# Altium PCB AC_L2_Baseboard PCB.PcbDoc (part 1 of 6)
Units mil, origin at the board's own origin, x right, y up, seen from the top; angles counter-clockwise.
Board outline 7290 x 7055 mil, 4 copper layers (Top Layer, Layer 1, Layer 2, Bottom Layer), stack 70.356 mil thick; 510 components, 285 nets, 1364 pads, 522 vias.
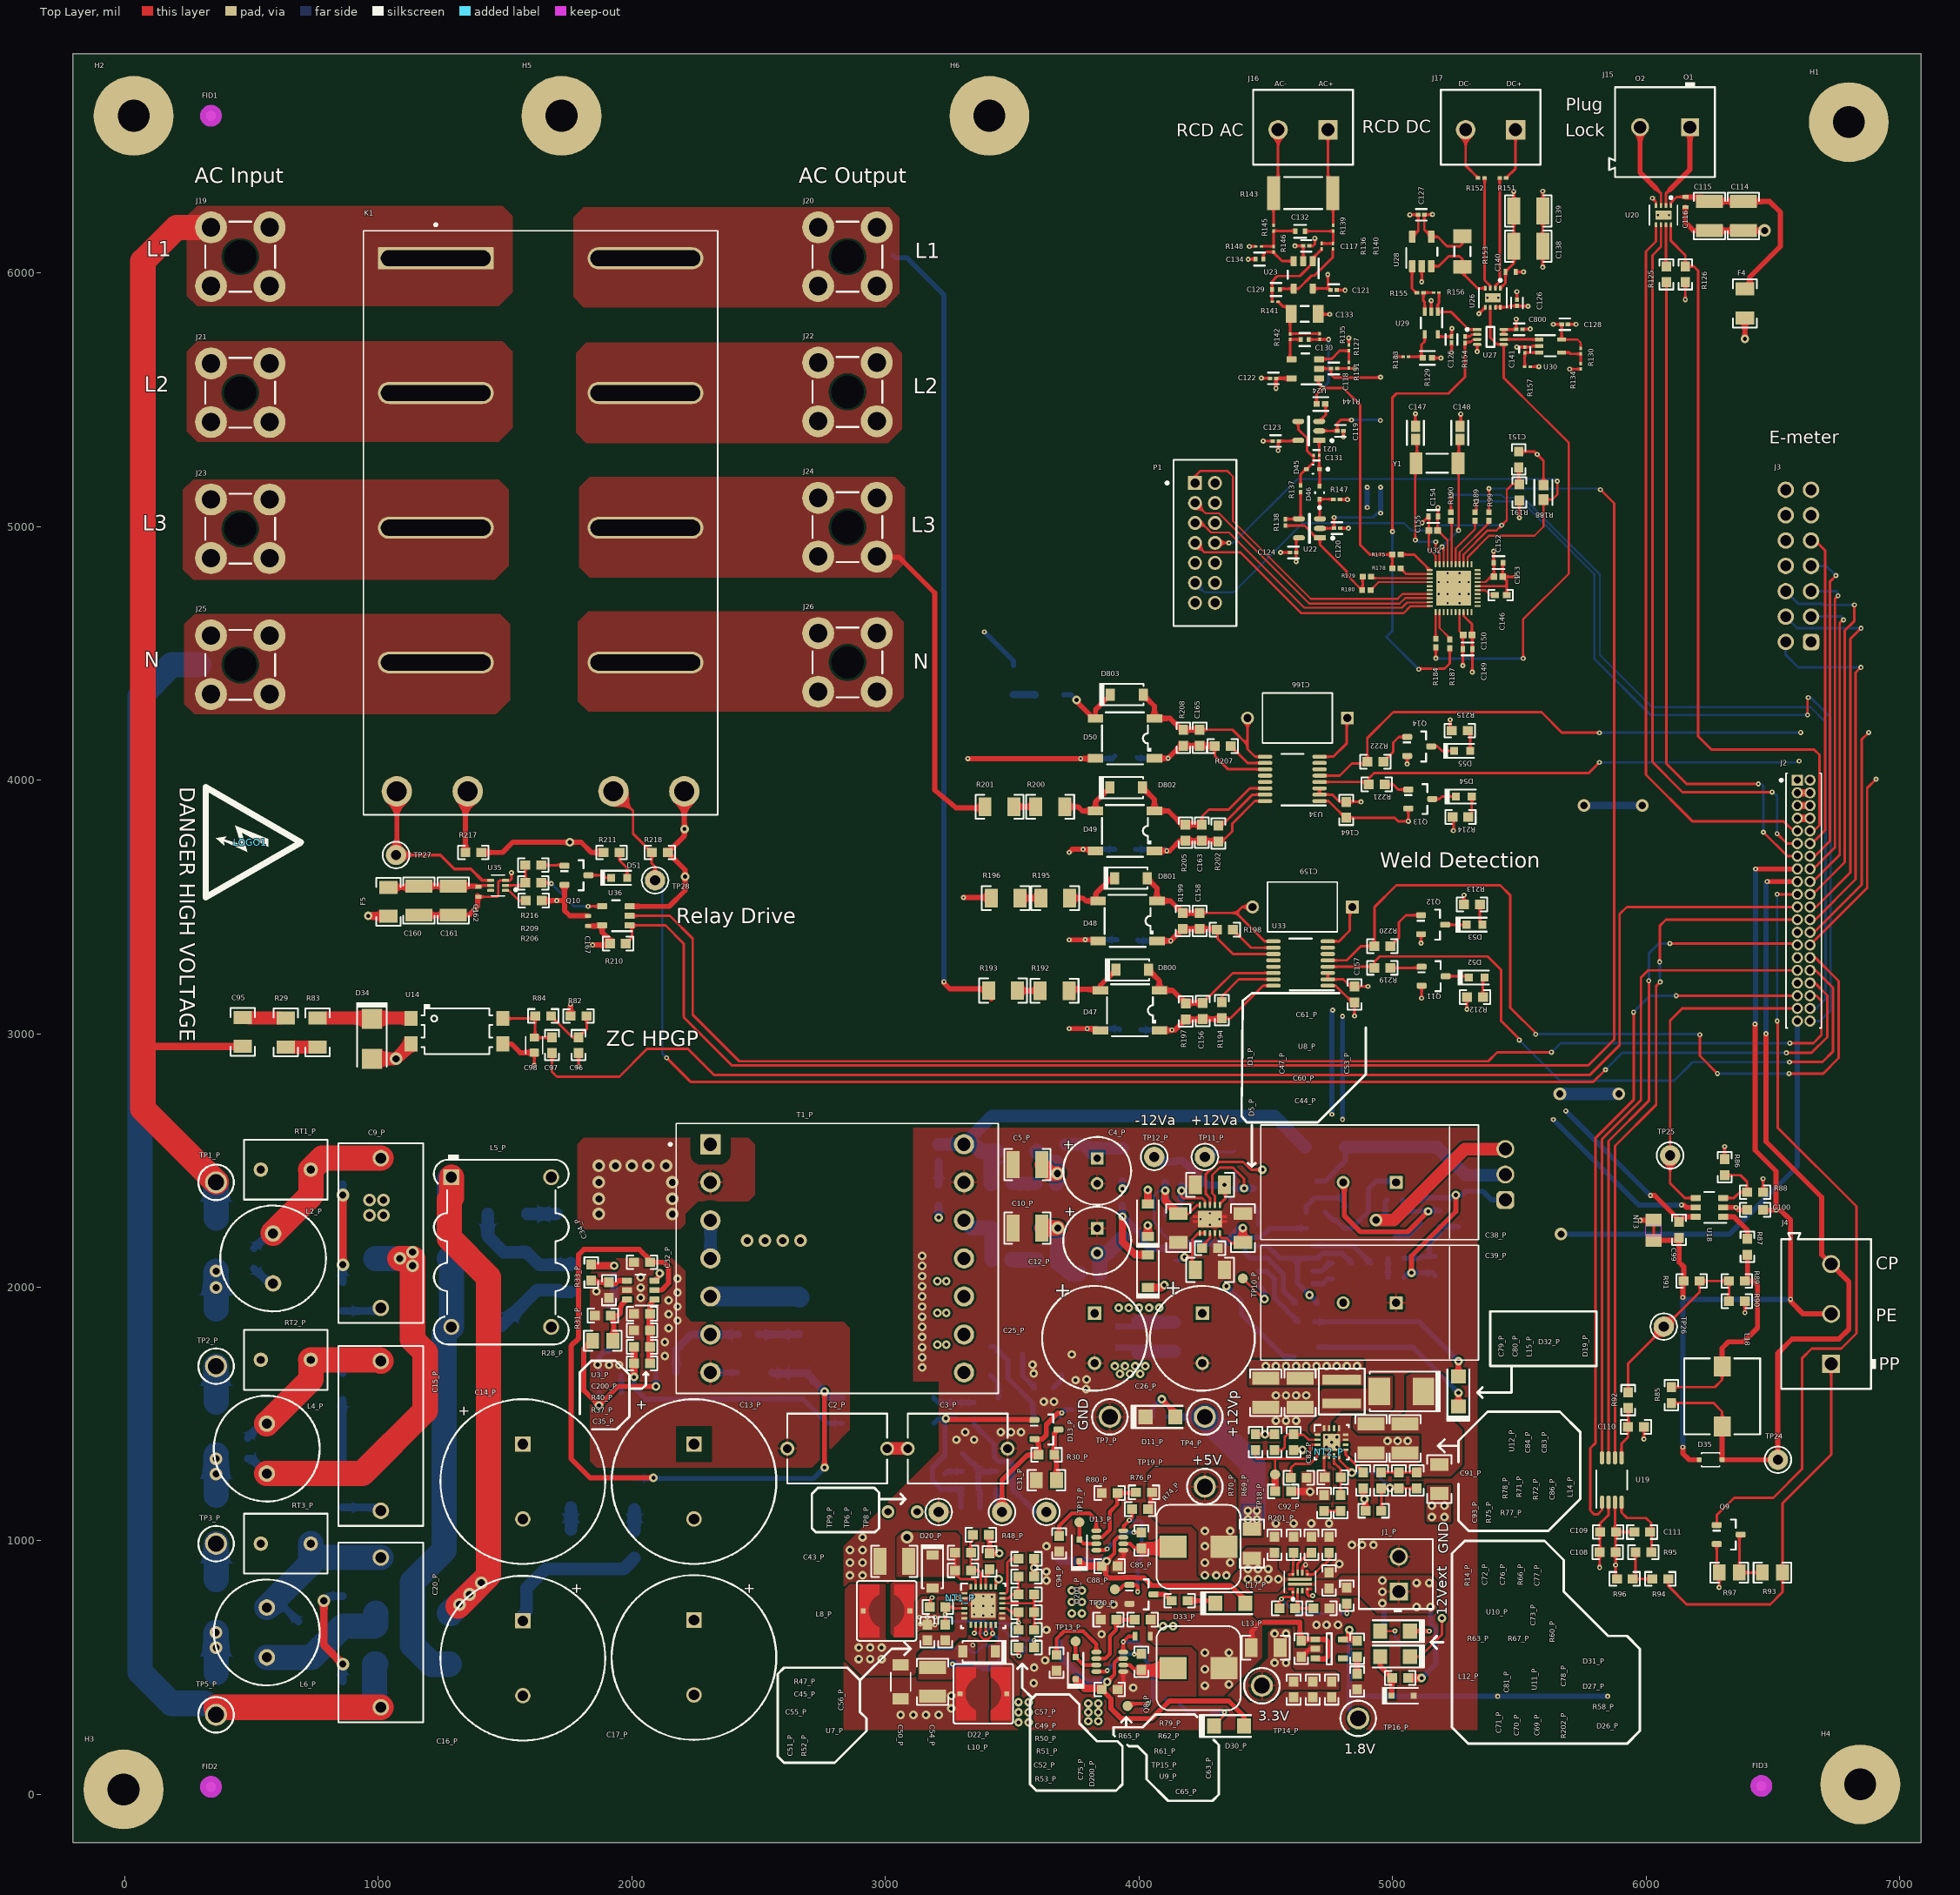
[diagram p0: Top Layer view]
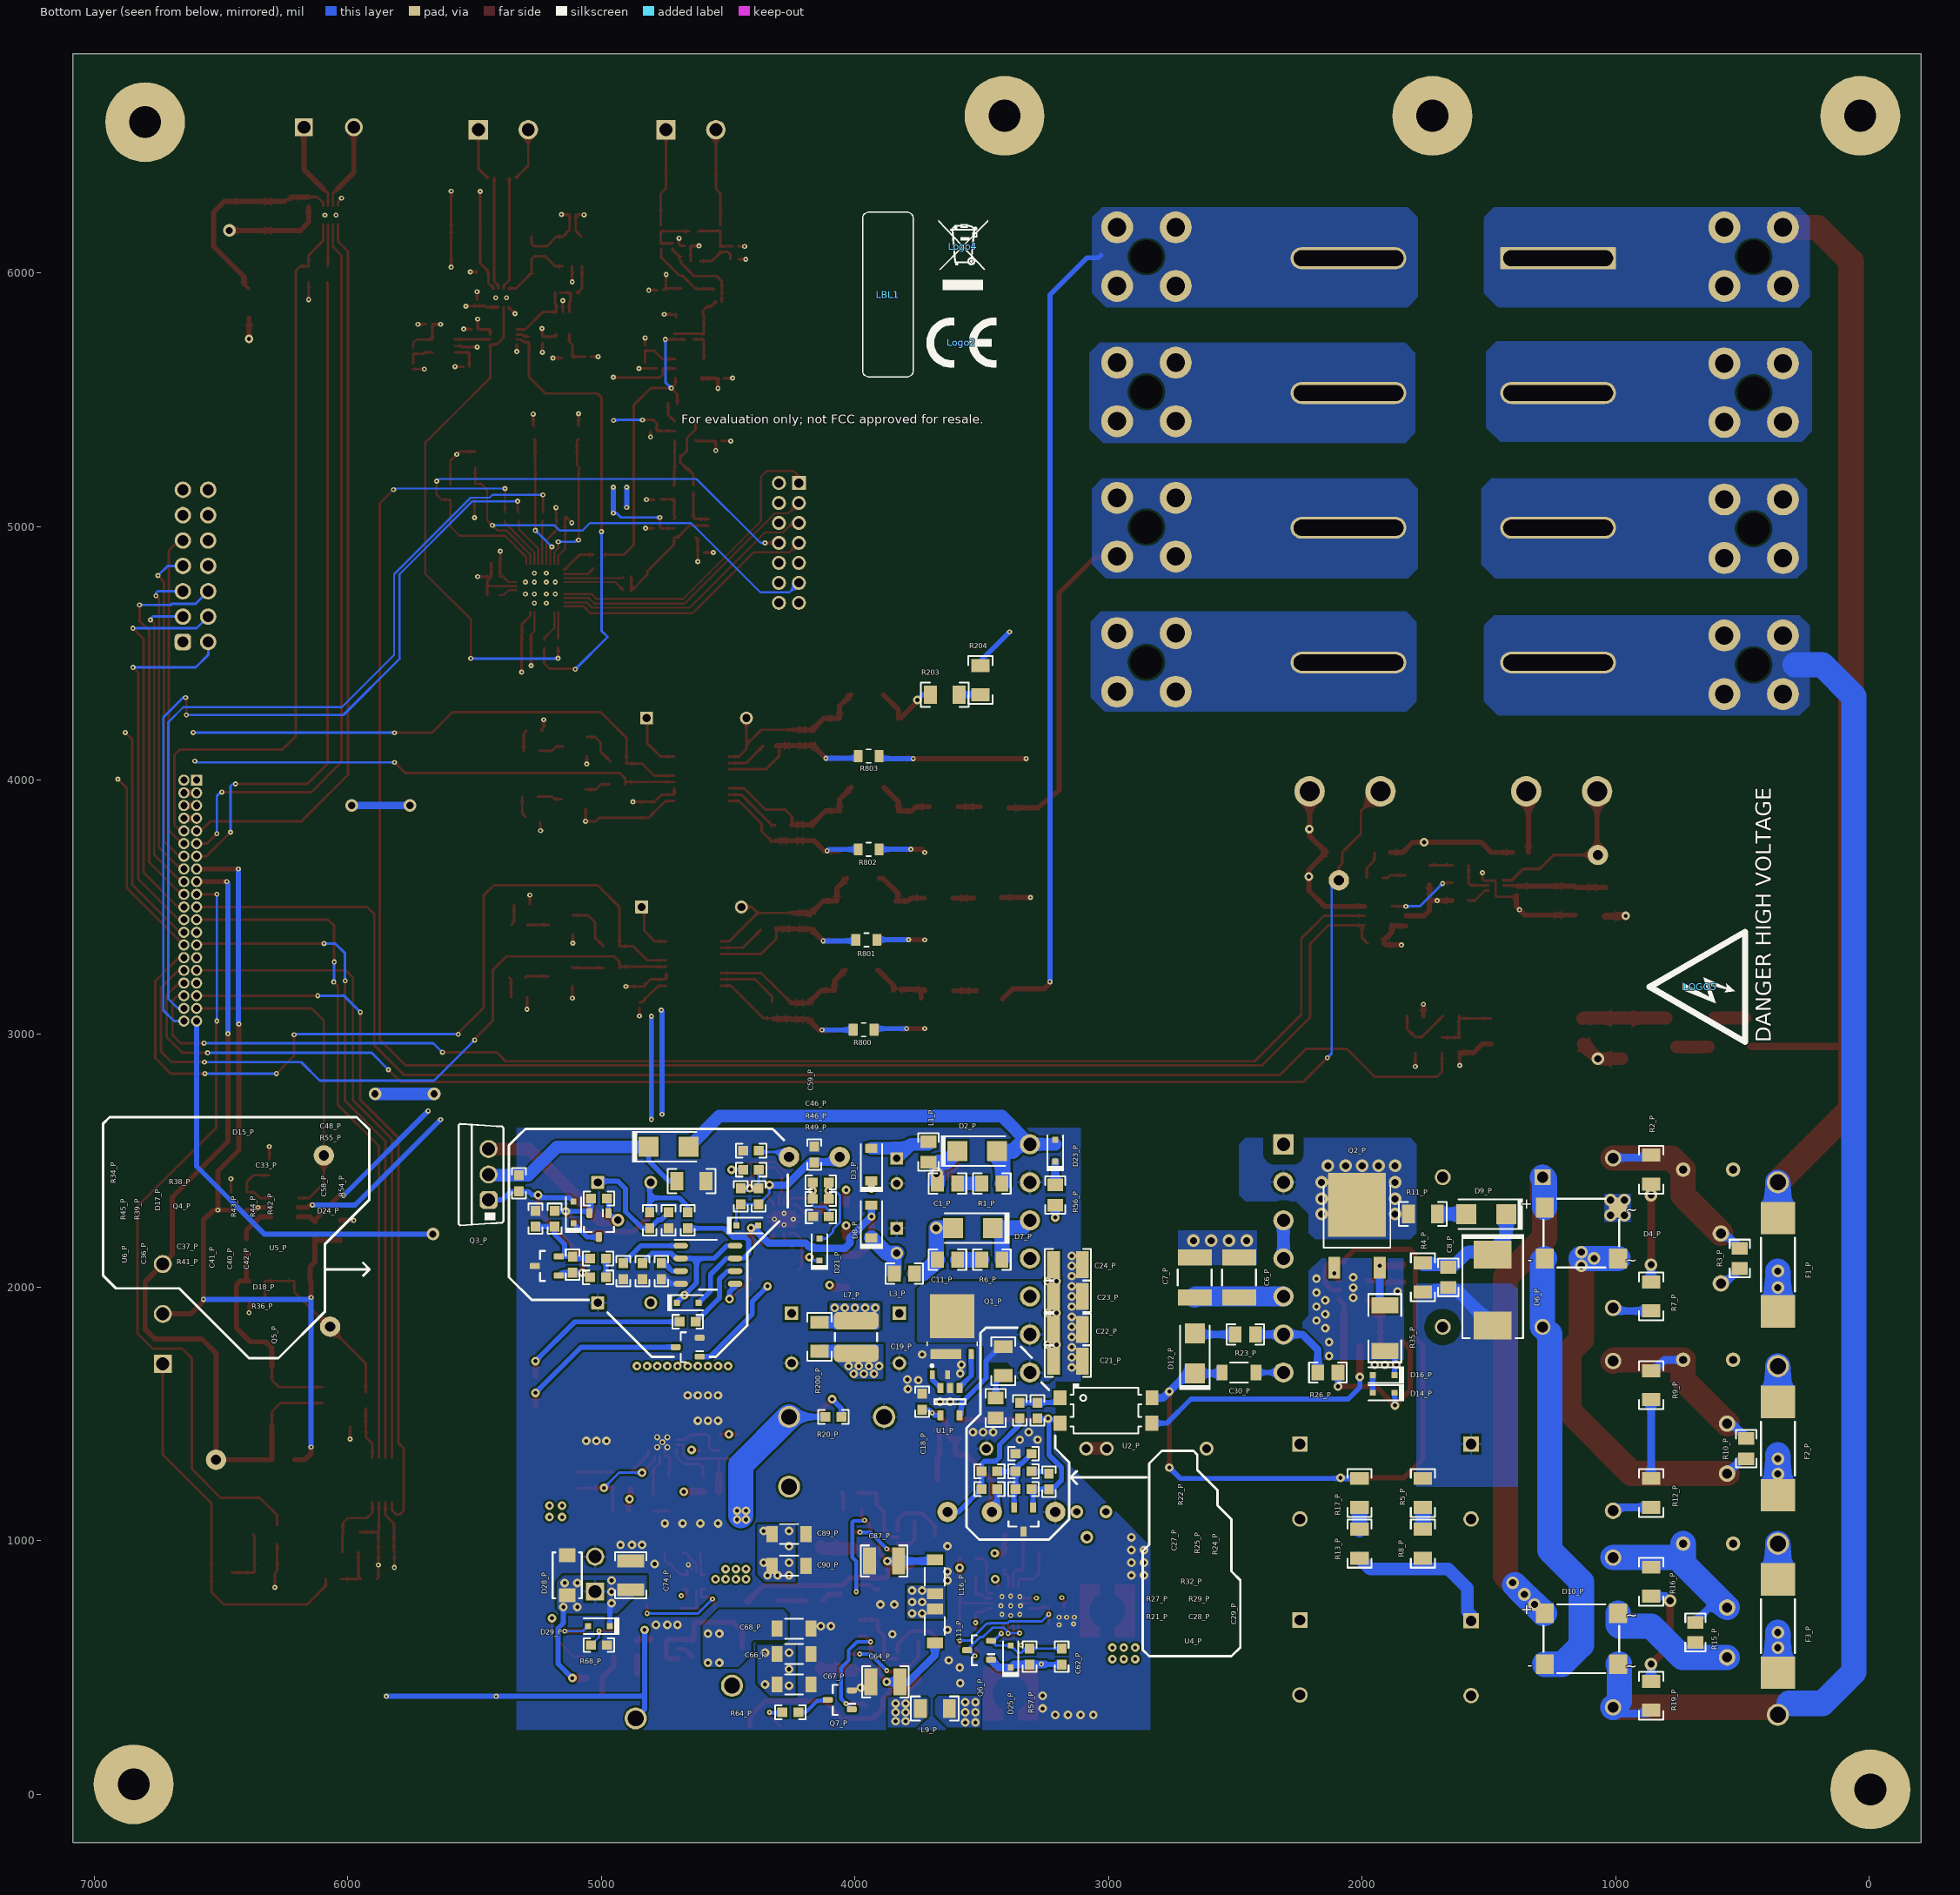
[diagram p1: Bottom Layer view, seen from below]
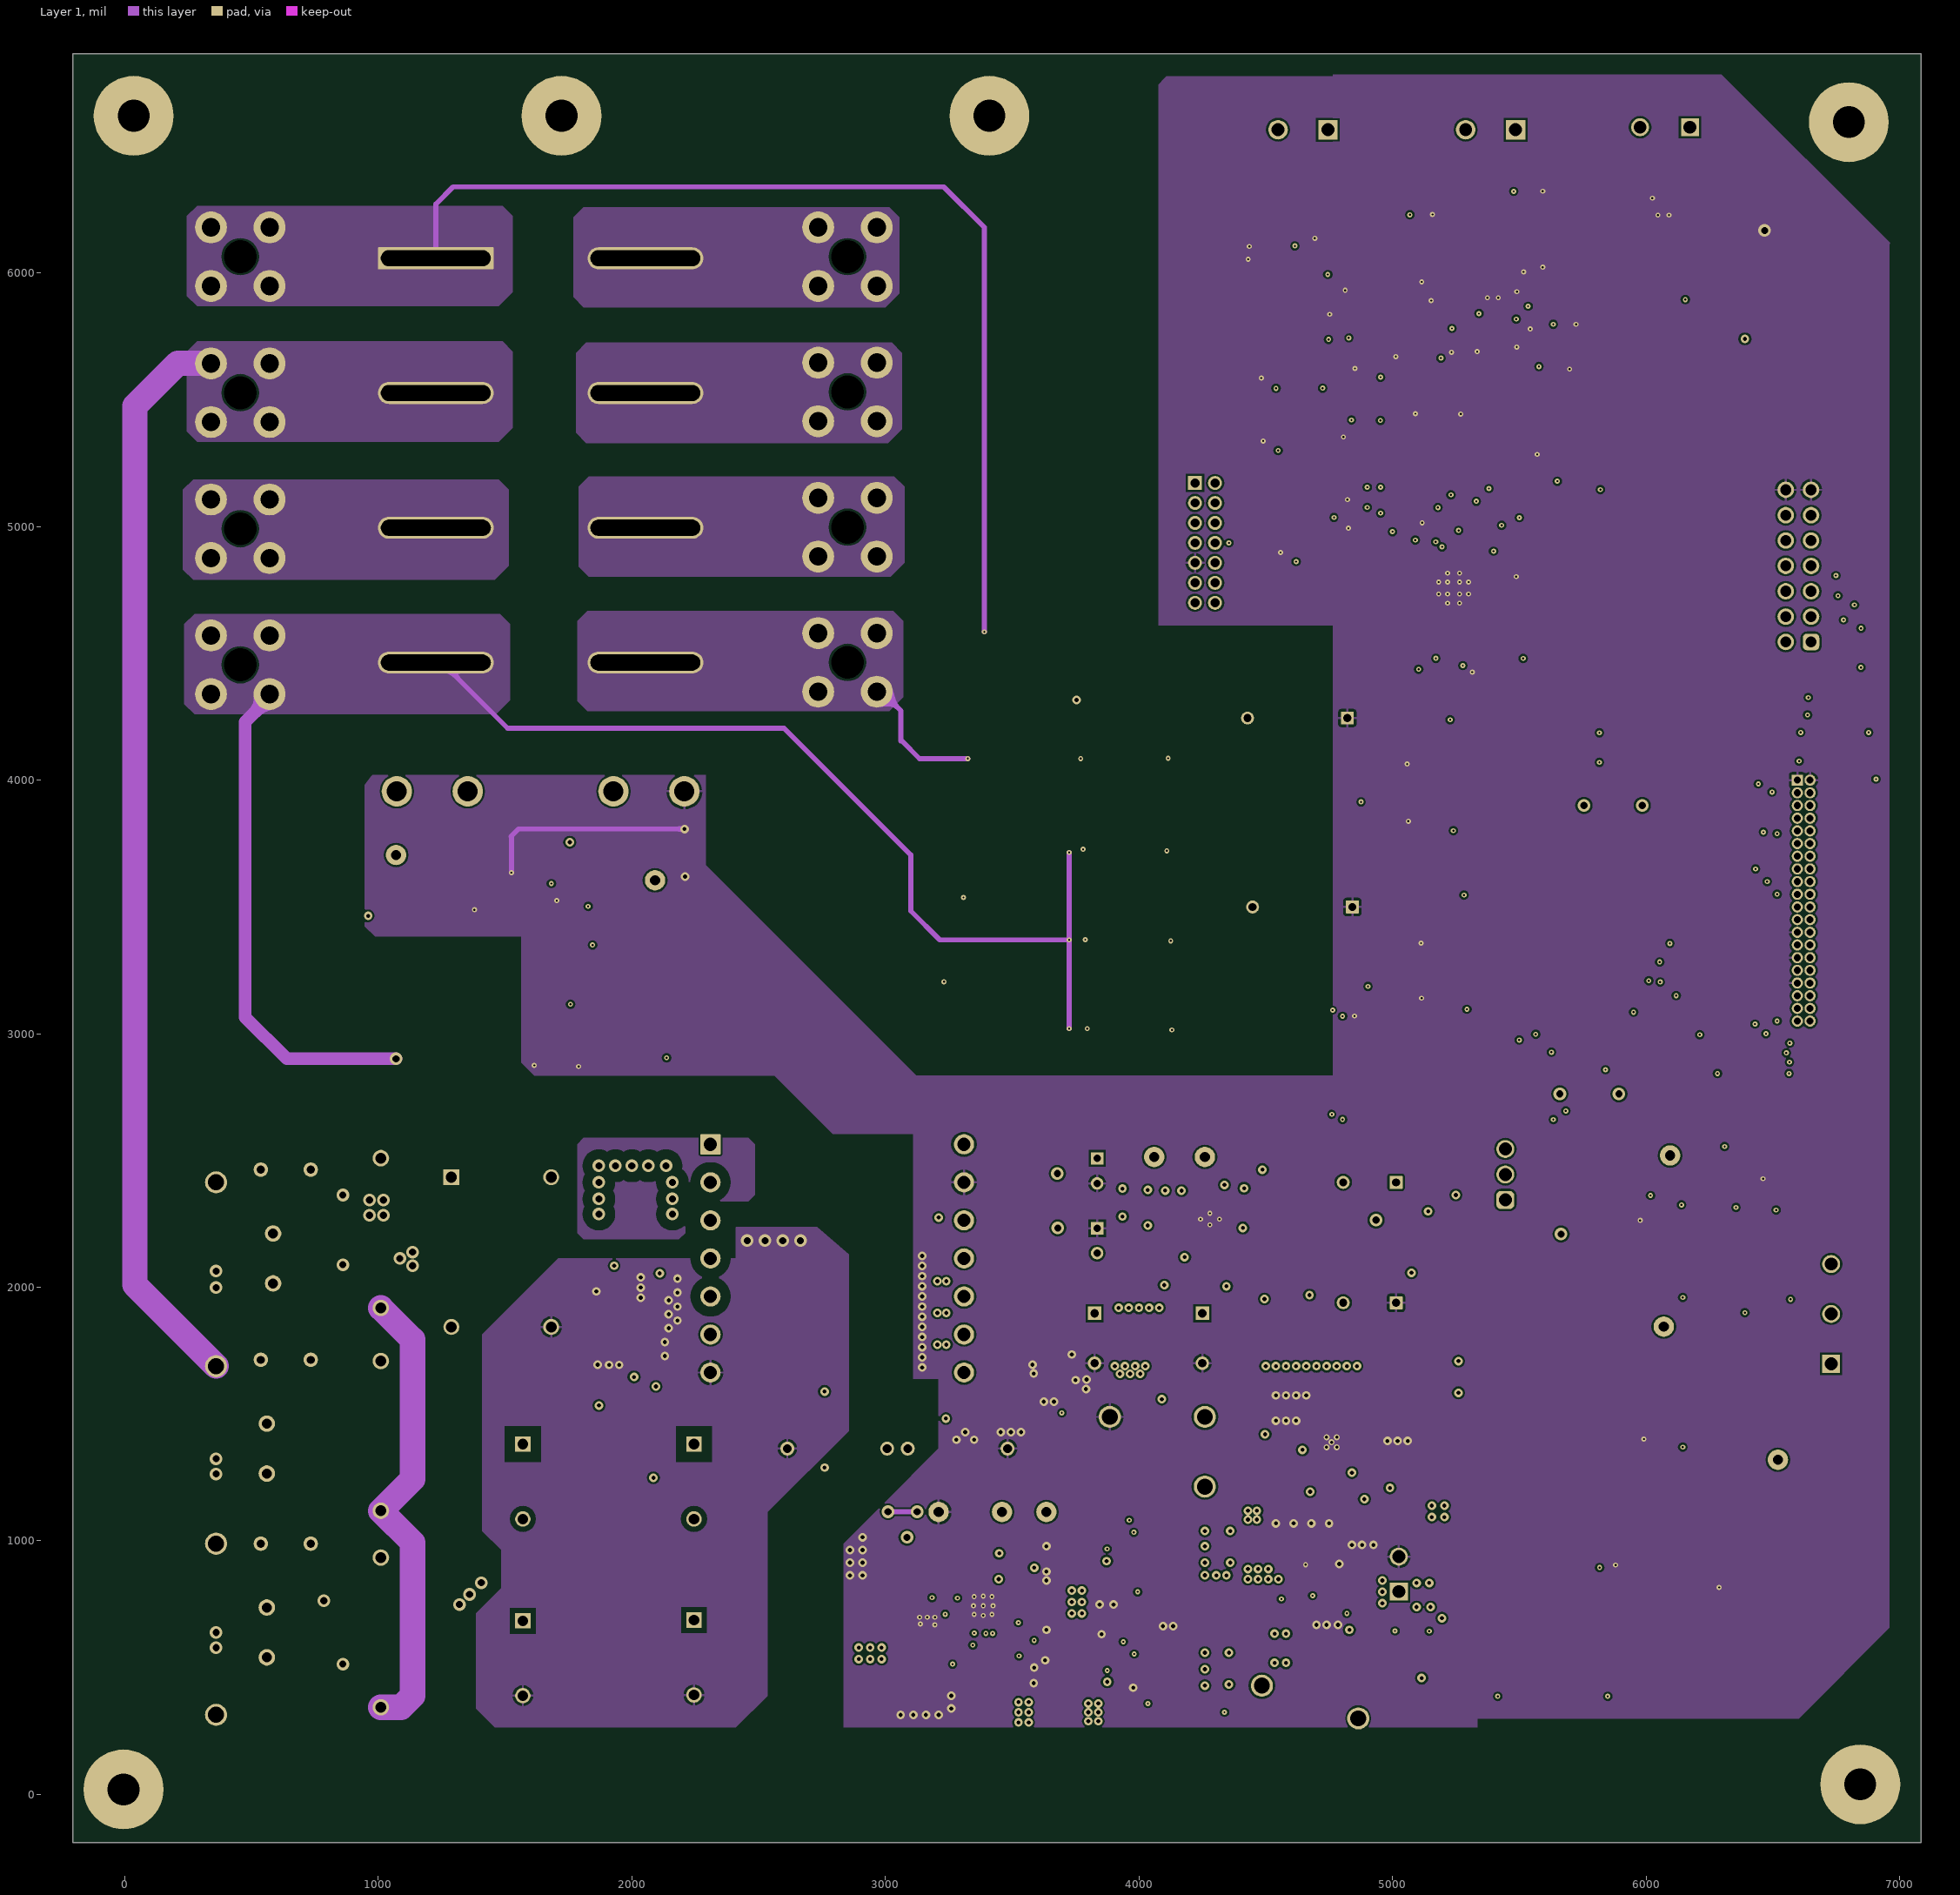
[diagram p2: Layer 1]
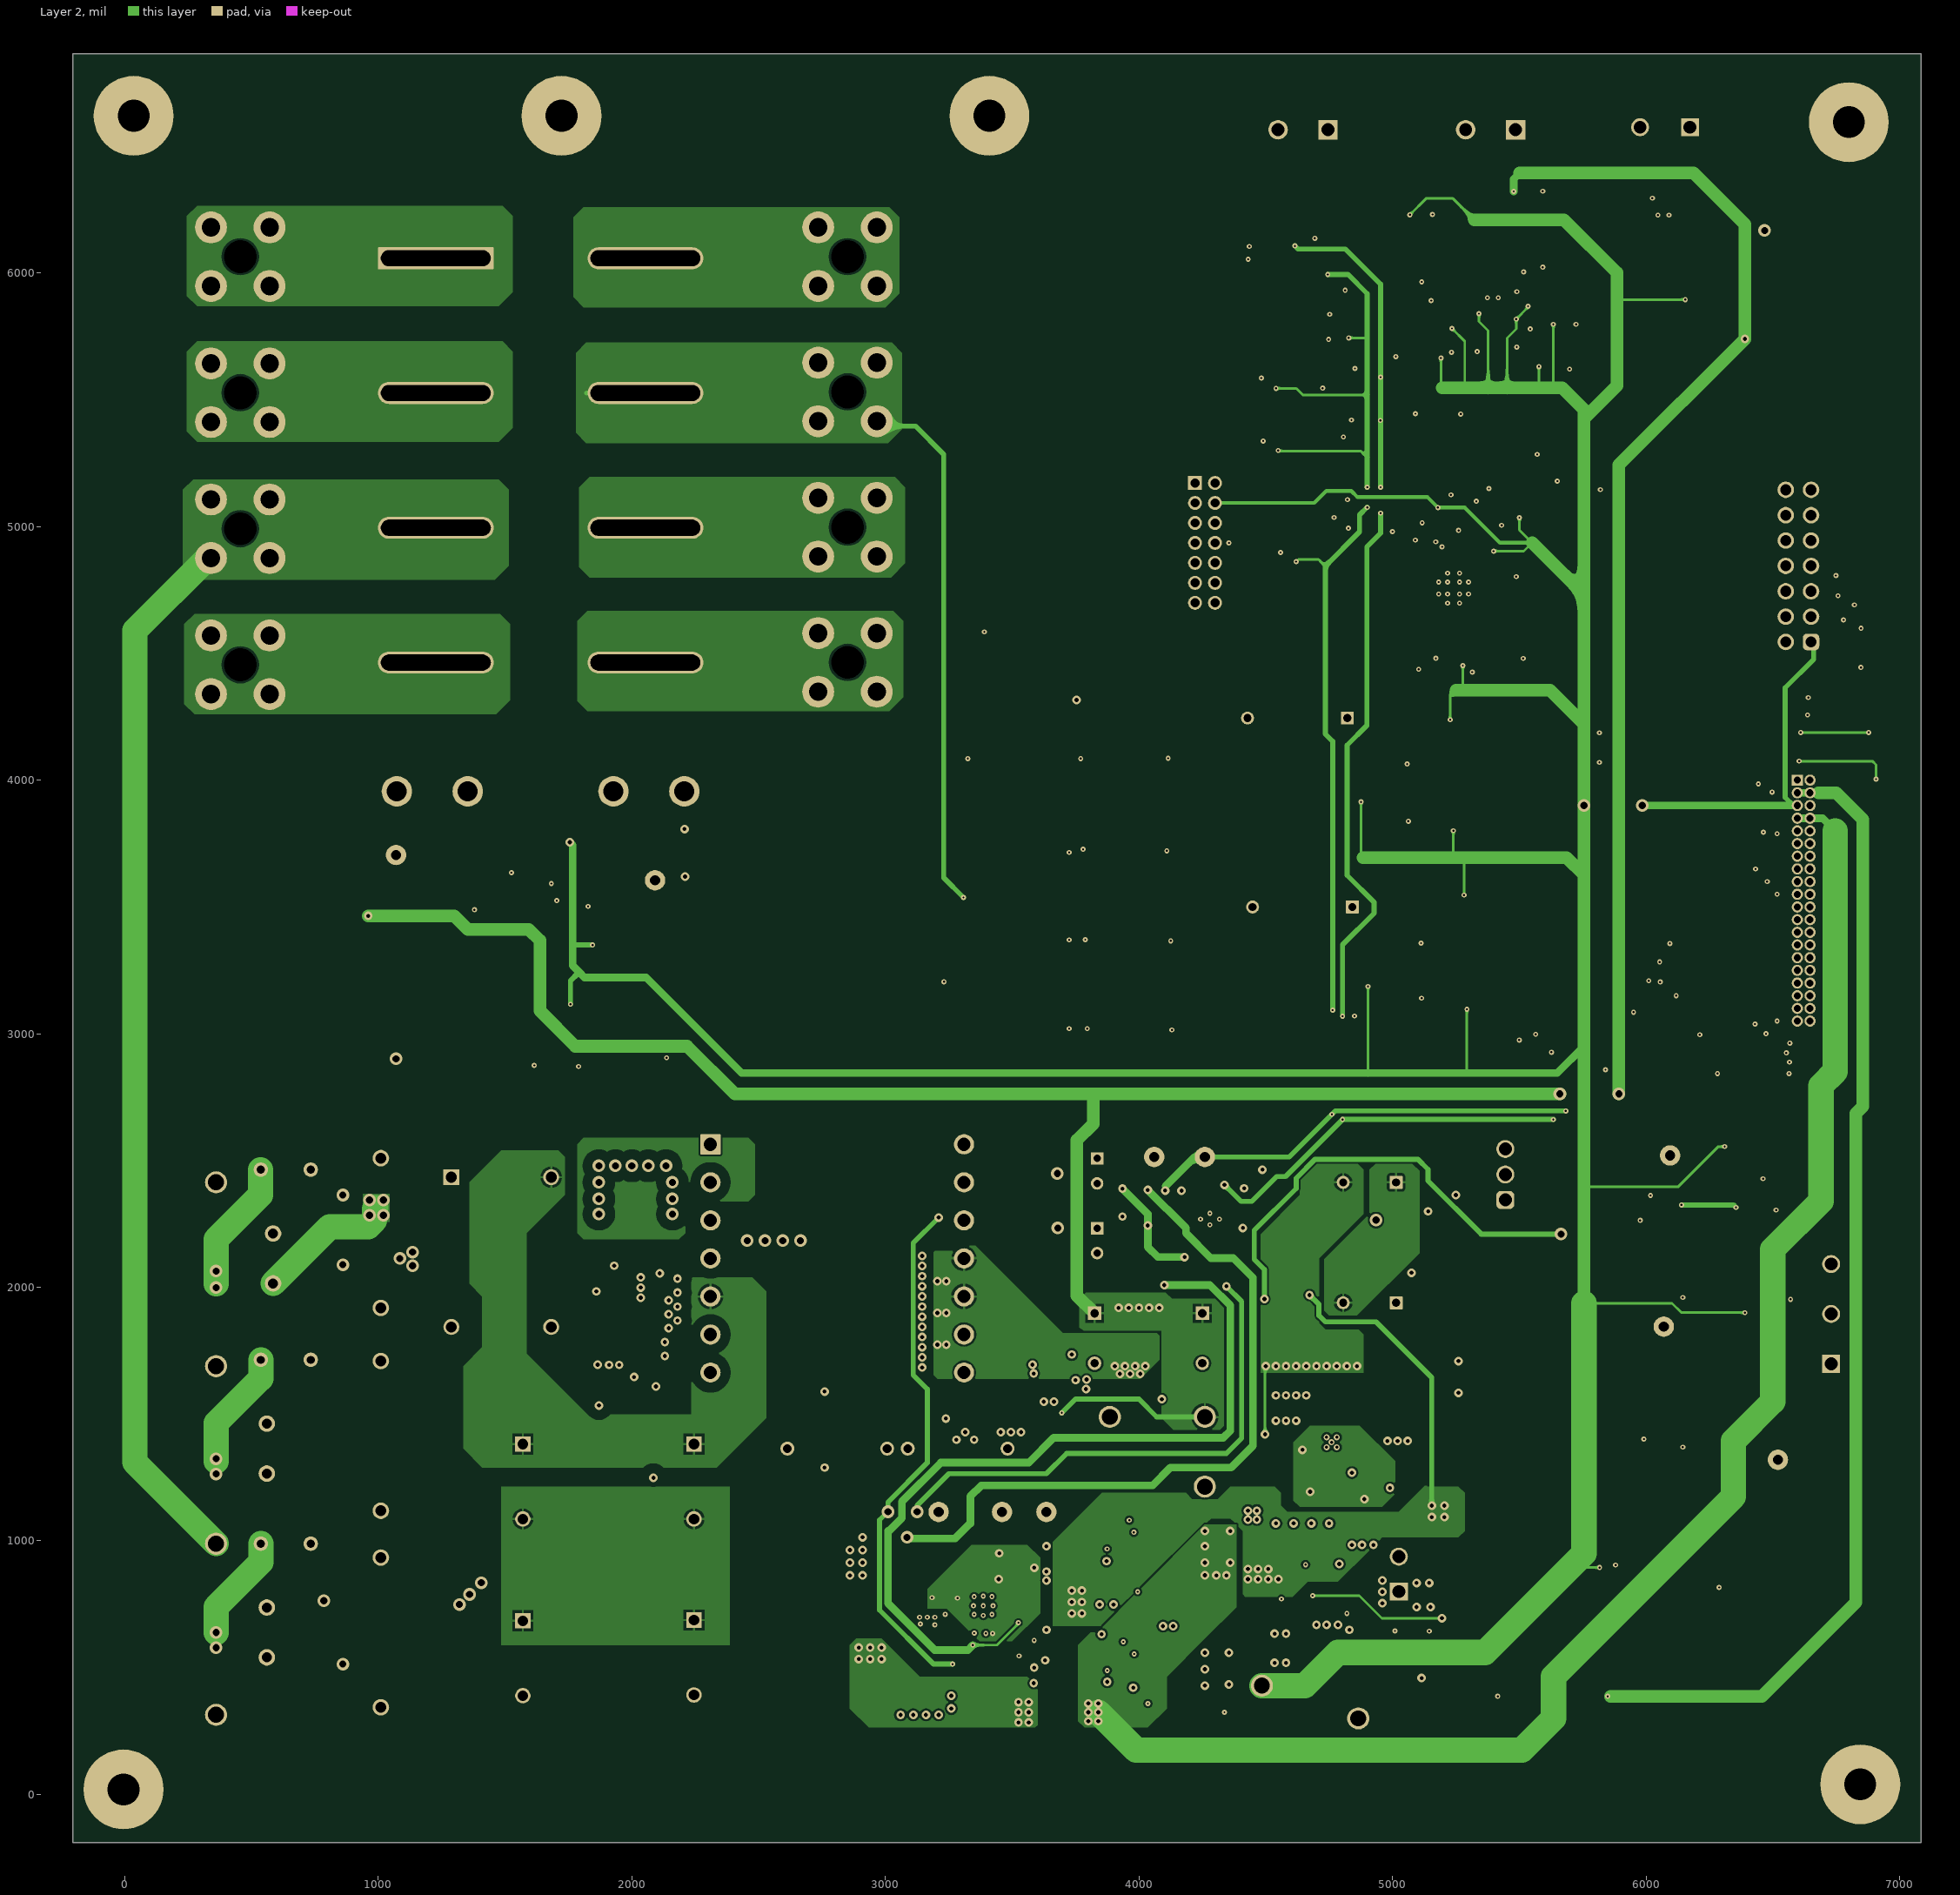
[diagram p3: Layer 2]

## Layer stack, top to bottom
Top Solder: solder mask 0.4, Solder Resist, Dk 3.5
Top Layer: signal copper 1.4
Dielectric 1: prepreg 2.8, PP-006, Dk 4.1
Layer 1: signal copper 1.378
Dielectric1: core 59.2, FR-4, Dk 4.8
Layer 2: signal copper 1.378
Dielectric 2: prepreg 2.8, PP-006, Dk 4.1
Bottom Layer: signal copper 1.4
Bottom Solder: solder mask 0.4, Solder Resist, Dk 3.5

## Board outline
-205,-190 -205,6865 7085,6865 7085,-190

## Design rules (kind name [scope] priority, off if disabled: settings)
AcuteAngle [All] p1: minimum=4.50000000000000E+0001 checktracksonly=FALSE
AssemblyTestPointUsage [All] p1: valid=2
BoardOutlineClearance BoardOutlineClearance_MountingHoles [OnCopper and InComponentClass('Mounting Holes')] p1: gap=40 ignorepadtopadclearanceinfootprint=FALSE
BoardOutlineClearance BoardOutlineClearance_Poly [OnCopper and IsPoly] p2: gap=25 ignorepadtopadclearanceinfootprint=FALSE
BoardOutlineClearance [OnCopper and Not InComponentClass('Logo') and not InComponentClass('FiducialMark') and not InRegion(1000,500,4000,800) and not InPoly] p3: gap=75 ignorepadtopadclearanceinfootprint=FALSE
Clearance Clearance_HV_AC [InNetClass('HV')] p1 off: gap=47.24 ignorepadtopadclearanceinfootprint=FALSE
Clearance "Schematic Clearance Constraint_28" [InNet('+14V_SW')] p2: gap=10 ignorepadtopadclearanceinfootprint=FALSE
Clearance "Schematic Clearance Constraint_20" [InNet('NetC6_P_1')] p3: gap=30 ignorepadtopadclearanceinfootprint=FALSE
Clearance "Schematic Clearance Constraint_19" [InNet('NetC8_P_2')] p4: gap=40 ignorepadtopadclearanceinfootprint=FALSE
Clearance "Schematic Clearance Constraint_18" [InNet('NetR5_P_1')] p5: gap=40 ignorepadtopadclearanceinfootprint=FALSE
Clearance "Schematic Clearance Constraint_17" [InNet('NetD9_P_2')] p6: gap=40 ignorepadtopadclearanceinfootprint=FALSE
Clearance "Schematic Clearance Constraint_16" [InNet('NetQ2_P_4')] p7: gap=40 ignorepadtopadclearanceinfootprint=FALSE
Clearance "Schematic Clearance Constraint_15" [InNet('NetT1_P_3')] p8: gap=40 ignorepadtopadclearanceinfootprint=FALSE
Clearance "Schematic Clearance Constraint_12" [InNet('NetR13_P_1')] p9: gap=20 ignorepadtopadclearanceinfootprint=FALSE
Clearance "Schematic Clearance Constraint_1" [InNet('NetC13_P_2')] p10: gap=20 ignorepadtopadclearanceinfootprint=FALSE
Clearance Clearance_Keepouts [((IsTrack Or IsArc) And Not InPoly) And IsFree and IsKeepOut vs ((IsTrack Or IsArc) And Not InPoly) And IsFree and IsKeepOut] p11: gap=0 ignorepadtopadclearanceinfootprint=FALSE
Clearance Clearance_Poly [InPolygon] p12: gap=8 ignorepadtopadclearanceinfootprint=FALSE
Clearance Clearance_FiducialMark [IsKeepOut and InComponentClass('FiducialMark') vs IsPad and InComponentClass('FiducialMark')] p13: gap=0 ignorepadtopadclearanceinfootprint=FALSE
Clearance [All] p14: gap=5 ignorepadtopadclearanceinfootprint=FALSE
ComponentClearance ComponentClearance_MountingHoles_FiducialMarks [InComponentClass('Mounting Holes') vs InComponentClass('FiducialMark')] p1: gap=50 collisioncheckmode=3 verticalgap=10 showdistances=FALSE
ComponentClearance ComponentClearance_Shunt [InComponentClass('Header') vs InComponentClass('Shunt')] p2: gap=0 collisioncheckmode=3 verticalgap=0 showdistances=FALSE
ComponentClearance ComponentClearance_Logo [InComponentClass('Logo')] p3: gap=50 collisioncheckmode=3 verticalgap=10 showdistances=FALSE
ComponentClearance ComponentClearance_ScrewToNut [(HasFootprint('NY PMS 440 0025 PH')) vs (HasFootprint('Keystone_1902C'))] p4: gap=5 collisioncheckmode=3 verticalgap=10 showdistances=FALSE
ComponentClearance ComponentClearance_MountingHoles [InComponentClass('Mounting Holes')] p5: gap=250 collisioncheckmode=3 verticalgap=100000 showdistances=FALSE
ComponentClearance ComponentClearance_SmallPassives [HasFootprint('0201*') or HasFootprint('0402*') or HasFootprint('0508') or HasFootprint('0603*') or HasFootprint('0612') or HasFootprint('0805*') or HasFootprint('0815*') or HasFootprint('0830*') or HasFootprint('1206*') or HasFootprint('1210*') or HasFootprint('1808*') or HasFootprint('1812*') or HasFootprint('1825*') or HasFootprint('2010*') or HasFootprint('2220*') or HasFootprint('2225*') or HasFootprint('2512*') or HasFootprint('2728*') or HasFootprint('3518*') vs HasFootprint('0201*') or HasFootprint('0402*') or HasFootprint('0508') or HasFootprint('0603*') or HasFootprint('0612') or HasFootprint('0805*') or HasFootprint('0815*') or HasFootprint('0830*') or HasFootprint('1206*') or HasFootprint('1210*') or HasFootprint('1808*') or HasFootprint('1812*') or HasFootprint('1825*') or HasFootprint('2010*') or HasFootprint('2220*') or HasFootprint('2225*') or HasFootprint('2512*') or HasFootprint('2728*') or HasFootprint('3518*')] p6: gap=14.96 collisioncheckmode=3 verticalgap=10 showdistances=FALSE
ComponentClearance ComponentClearance_THtoSMT [IsThruComponent vs IsSMTComponent] p7: gap=25 collisioncheckmode=3 verticalgap=30 showdistances=FALSE
ComponentClearance ComponentClearance_THtoTH [IsThruComponent vs IsThruComponent] p8 off: gap=30 collisioncheckmode=3 verticalgap=30 showdistances=FALSE
ComponentClearance [All] p9 off: gap=30 collisioncheckmode=3 verticalgap=10 showdistances=FALSE
DiffPairsRouting [All] p1: maxlimit=100 minlimit=10 mostfreqgap=10 toplayer_minwidth=15 toplayer_maxwidth=15 toplayer_prefwidth=15 midlayer1_minwidth=15 midlayer1_maxwidth=15 midlayer1_prefwidth=15 midlayer2_minwidth=15 midlayer2_maxwidth=15 midlayer2_prefwidth=15 bottomlayer_minwidth=15 bottomlayer_maxwidth=15 bottomlayer_prefwidth=15 maxuncoupledlength=1000
FabricationTestPointUsage TestPointUsage [All] p1: valid=2 allowmultiple=FALSE
FabricationTestpoint Testpoint [All] p1: side=3 testpointundercomponent=TRUE minsize=40 maxsize=100 preferedsize=60 minholesize=0 maxholesize=40 preferedholesize=32 testpointgrid=1 allowsidetop=TRUE allowsidebottom=TRUE usegrid=TRUE gridtolerance=0.01
FanoutControl Fanout_LCC [IsLCC] p1: bgadir=Out bgaviamode=Centered fanoutstyle=Auto fanoutdirection=Alternating viagrid=1 // Fanout_LCC (Default Rule)
FanoutControl Fanout_BGA [IsBGA] p2: bgadir=Out bgaviamode=Centered fanoutstyle=Auto fanoutdirection=Alternating viagrid=1 // Fanout_BGA (Default Rule)
FanoutControl Fanout_Default [All] p4: bgadir=Out bgaviamode=Centered fanoutstyle=Auto fanoutdirection=Alternating viagrid=1 // Fanout_Default (Default Rule)
FanoutControl Fanout_Small [(CompPinCount < 5)] p5: bgadir=Out bgaviamode=Centered fanoutstyle=Auto fanoutdirection=OutThenIn viagrid=1 // Fanout_Small (Default Rule)
Height [All] p1: minheight=0 maxheight=1100 prefheight=500
HoleSize HoleSize_Relay [(InNetClass('HV') AND InPadClass('All Pads'))] p1: absolutevalues=TRUE maxlimit=435 minlimit=1 maxpercent=80.000 minpercent=20.000
HoleSize [All] p2: absolutevalues=TRUE maxlimit=251 minlimit=7.87 maxpercent=80.000 minpercent=20.000
MinimumAnnularRing MinimumAnnularRing_ThermalPadVias [IsVia and InAnyComponent] p1: minimumring=5.9
MinimumAnnularRing [All] p2: minimumring=5.9
MinimumSolderMaskSliver MinimumSolderMaskSliver_ISO1212 [HasFootprint('DBQ0016A_N')] p1: minsoldermaskwidth=1.25
MinimumSolderMaskSliver MinimumSolderMaskSliver_TPS6513 [HasFootprint('RGE0024B')] p2: minsoldermaskwidth=1.8
MinimumSolderMaskSliver MinimumSolderMaskSliver_TLV7011 [HasFootprint('DCK0005A_N')] p3: minsoldermaskwidth=1.8
MinimumSolderMaskSliver MinimumSolderMaskSliver_TPS55330 [HasFootprint('RTE0016C_NV')] p4: minsoldermaskwidth=2.2
MinimumSolderMaskSliver MinimumSolderMaskSliver_INA293 [HasFootprint('DBV0005A_M')] p5: minsoldermaskwidth=3.8
MinimumSolderMaskSliver MinimumSolderMaskSliver_TPS7A3901_1 [HasFootprint('DSC0010J')] p6: minsoldermaskwidth=2.2
MinimumSolderMaskSliver MinimumSolderMaskSliver_Res [HasFootprint('RESC1005X40X25NL05T10')] p7: minsoldermaskwidth=1.8
MinimumSolderMaskSliver MinimumSolderMaskSliver_Logo [InComponentClass('Logo') vs InComponentClass('Logo')] p8: minsoldermaskwidth=0.7
MinimumSolderMaskSliver [All] p9: minsoldermaskwidth=3.94
PlaneConnect [All] p1: planeconnectstyle=Direct reliefexpansion=10 reliefentries=4 reliefconductorwidth=10 reliefairgap=10
PolygonConnect PolygonConnect_4 [All vs IsNamedPolygon('LAYER_2_LINE1_IN_P1412') Or IsNamedPolygon('LAYER_2_LINE1_OUT_P1420') Or IsNamedPolygon('LAYER_2_LINE2_IN_P1414') Or IsNamedPolygon('LAYER_2_LINE2_OUT_P1422') Or IsNamedPolygon('LAYER_2_LINE3_IN_P1416') Or IsNamedPolygon('LAYER_2_LINE3_OUT_P1424') Or IsNamedPolygon('LAYER_2_N_IN_P1418') Or IsNamedPolygon('LAYER_2_N_OUT_P1426')] p1: connectstyle=Direct reliefconductorwidth=10 reliefentries=4 polygonreliefangle="90 Angle" airgapwidth=10
PolygonConnect PolygonConnect_3 [All vs IsNamedPolygon('LAYER_1_LINE1_IN_P1411') Or IsNamedPolygon('LAYER_1_LINE1_OUT_P1419') Or IsNamedPolygon('LAYER_1_LINE2_IN_P1413') Or IsNamedPolygon('LAYER_1_LINE2_OUT_P1421') Or IsNamedPolygon('LAYER_1_LINE3_IN_P1415') Or IsNamedPolygon('LAYER_1_LINE3_OUT_P1423') Or IsNamedPolygon('LAYER_1_N_IN_P1417') Or IsNamedPolygon('LAYER_1_N_OUT_P1425')] p2: connectstyle=Direct reliefconductorwidth=10 reliefentries=4 polygonreliefangle="90 Angle" airgapwidth=10
PolygonConnect PolygonConnect_2 [All vs IsNamedPolygon('TOP_LAYER_N_IN_P1382') Or IsNamedPolygon('TOP_LAYER_N_OUT_P1366') Or IsNamedPolygon('BOTTOM_LAYER_N_IN_P1390') Or IsNamedPolygon('BOTTOM_LAYER_N_OUT_P1392')] p3: connectstyle=Direct reliefconductorwidth=10 reliefentries=4 polygonreliefangle="90 Angle" airgapwidth=10
PolygonConnect PolygonConnect_1 [All vs IsNamedPolygon('TOP_LAYER_LINE1_IN_P1378') Or IsNamedPolygon('TOP_LAYER_LINE1_OUT_P1370') Or IsNamedPolygon('TOP_LAYER_LINE2_IN_P1374') Or IsNamedPolygon('TOP_LAYER_LINE2_OUT_P1330') Or IsNamedPolygon('TOP_LAYER_LINE3_IN_P1380') Or IsNamedPolygon('TOP_LAYER_LINE3_OUT_P1372') Or IsNamedPolygon('BOTTOM_LAYER_LINE1_IN_P1256') Or IsNamedPolygon('BOTTOM_LAYER_LINE1_OUT_P1398') Or IsNamedPolygon('BOTTOM_LAYER_LINE2_IN_P1386') Or IsNamedPolygon('BOTTOM_LAYER_LINE2_OUT_P1396') Or IsNamedPolygon('BOTTOM_LAYER_LINE3_IN_P1388') Or IsNamedPolygon('BOTTOM_LAYER_LINE3_OUT_P1394')] p4: connectstyle=Direct reliefconductorwidth=10 reliefentries=4 polygonreliefangle="90 Angle" airgapwidth=10
PolygonConnect [InNetClass('All Nets')] p5: thpad.connectstyle=Relief thpad.reliefconductorwidth=10 thpad.reliefentries=4 thpad.polygonreliefangle="90 Angle" thpad.airgapwidth=10 smdpad.connectstyle=Direct smdpad.reliefconductorwidth=10 smdpad.reliefentries=4 smdpad.polygonreliefangle="90 Angle" smdpad.airgapwidth=10 via.connectstyle=Direct via.reliefconductorwidth=10 via.reliefentries=4 via.polygonreliefangle="90 Angle" via.airgapwidth=10
RoutingVias ThermalPadVias [IsVia and InAnyComponent] p1: holewidth=7.87 width=19.68 viastyle="Through Hole" minholewidth=7.87 minwidth=19.68 maxholewidth=12.99 maxwidth=23.62
RoutingVias [All] p2: holewidth=16 width=34 viastyle="Through Hole" minholewidth=6 minwidth=15 maxholewidth=40 maxwidth=65
SilkToBoardRegionClearance [Not ((IsComment or IsDesignator) And (Hide <> 'False')) and not InRegion(1000,500,4000,800)] p1:
SilkToSilkClearance SilkToSilkClearance_Pb-FreeLogo [(HasFootprint('Pb-Free_Overlay_Medium') OR HasFootprint('Pb-Free_Overlay_Small')) vs (HasFootprint('Pb-Free_Overlay_Medium') OR HasFootprint('Pb-Free_Overlay_Small'))] p1: silktosilkclearance=0
SilkToSilkClearance [All] p2: silktosilkclearance=2
SilkToSolderMaskClearance SilkToComponentPadClearance_FillArea [IsFill and InAnycomponent] p1: minsilkscreentomaskgap=1.5 clearancetoexposedcopper=TRUE
SilkToSolderMaskClearance SilkToComponentPadClearance_Pad [IsPad and InAnycomponent] p2: minsilkscreentomaskgap=3 clearancetoexposedcopper=TRUE
SilkToSolderMaskClearance SilkToComponentPadClearance_1 [(IsPad or IsFill or IsRegion) and InAnycomponent] p3: minsilkscreentomaskgap=5 clearancetoexposedcopper=TRUE
SilkToSolderMaskClearance "Silk to Solder Mask Opening" [All] p4: minsilkscreentomaskgap=3 clearancetoexposedcopper=FALSE
SolderMaskExpansion [All] p1 off: expansion=1.97
Width Width_5V [All] p1 off: maxlimit=100 minlimit=10 preferedwidth=30
Width Width_-12a [InNet('-12Va')] p2 off: maxlimit=50 minlimit=10 preferedwidth=20
Width Width_12a [InNet('+12Va')] p3 off: maxlimit=50 minlimit=10 preferedwidth=20
Width Width_12VP [InNet('12V_In')] p4 off: maxlimit=50 minlimit=10 preferedwidth=30
Width Width_3_3 [InNet('3V3')] p5 off: maxlimit=100 minlimit=10 preferedwidth=30
Width Width_GND [InNet('PGND')] p6 off: maxlimit=30 minlimit=10 preferedwidth=20
Width Width_AC [InNetClass('HV')] p7 off: maxlimit=200 minlimit=20 preferedwidth=100
Width [All] p8 off: maxlimit=20 minlimit=8 preferedwidth=10 checkconnectedcopper=TRUE
14 further rules are at their usual default settings.

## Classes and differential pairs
component class "AC_L2_Baseboard SCH-POL_PWR": C43_P C44_P C45_P C46_P C47_P C48_P C49_P C50_P C51_P C52_P C53_P C54_P C55_P C56_P C57_P C58_P C59_P C60_P C61_P C62_P C63_P C64_P C65_P C66_P C67_P C68_P C69_P C70_P C71_P C72_P C73_P C74_P C75_P C76_P C77_P C78_P C79_P C80_P C81_P C82_P C83_P C84_P C85_P C86_P C87_P C88_P C89_P C90_P C91_P C92_P C93_P C94_P D20_P D21_P D22_P D23_P D24_P D25_P D26_P D27_P D28_P D29_P D30_P D31_P D32_P D33_P D200_P D201_P J1_P L8_P L9_P L10_P L11_P L12_P L13_P L14_P L15_P L16_P L17_P NT1_P NT2_P Q6_P Q7_P Q8_P R46_P R47_P R48_P R49_P R50_P R51_P R52_P R53_P R54_P R55_P R56_P R57_P R58_P R60_P R61_P R62_P R63_P R64_P R65_P R66_P R67_P R68_P R69_P R70_P R71_P R72_P R74_P R75_P R76_P R77_P R78_P R79_P R80_P R201_P R202_P TP11_P TP12_P TP13_P TP14_P TP15_P TP16_P TP17_P TP18_P TP19_P TP20_P U7_P U8_P U9_P U10_P U11_P U12_P U13_P
component class "AC_L2_Baseboard SCH-Flyback_PWR": C1_P C2_P C3_P C4_P C5_P C6_P C7_P C8_P C9_P C10_P C11_P C12_P C13_P C14_P C15_P C16_P C17_P C18_P C19_P C20_P C21_P C22_P C23_P C24_P C25_P C26_P C27_P C28_P C29_P C30_P C31_P C32_P C33_P C34_P C35_P C36_P C37_P C38_P C39_P C40_P C41_P C42_P C200_P D1_P D2_P D3_P D4_P D5_P D6_P D7_P D8_P D9_P D10_P D11_P D12_P D13_P D14_P D15_P D16_P D17_P D18_P D19_P F1_P F2_P F3_P L1_P L2_P L3_P L4_P L5_P L6_P L7_P Q1_P Q2_P Q3_P Q4_P Q5_P R1_P R2_P R3_P R4_P R5_P R6_P R7_P R8_P R9_P R10_P R11_P R12_P R13_P R14_P R15_P R16_P R17_P R19_P R20_P R21_P R22_P R23_P R24_P R25_P R26_P R27_P R28_P R29_P R30_P R31_P R32_P R33_P R34_P R35_P R36_P R37_P R38_P R39_P R40_P R41_P R42_P R43_P R44_P R45_P R200_P RT1_P RT2_P RT3_P T1_P TP1_P TP2_P TP3_P TP4_P TP5_P TP6_P TP7_P TP8_P TP9_P TP10_P U1_P U2_P U3_P U4_P U5_P U6_P
net class HV: LINE1_IN LINE1_OUT LINE2_IN LINE2_OUT LINE3_IN LINE3_OUT N_IN N_OUT
component class "Mounting Holes": H1 H2 H3 H4 H5 H6
component class Label: LBL1
component class Header: J3
component class FiducialMark: FID1 FID2 FID3
component class AC_L2_Baseboard_Relay_Weld_Detect: C156 C157 C158 C159 C160 C161 C162 C163 C164 C165 C166 C167 D47 D48 D49 D50 D51 D52 D53 D54 D55 D800 D801 D802 D803 F5 J19 J20 J21 J22 J23 J24 J25 J26 K1 Q10 Q11 Q12 Q13 Q14 R192 R193 R194 R195 R196 R197 R198 R199 R200 R201 R202 R203 R204 R205 R206 R207 R208 R209 R210 R211 R212 R213 R214 R215 R216 R217 R218 R219 R220 R221 R222 R800 R801 R802 R803 TP27 TP28 U33 U34 U35 U36
component class AC_L2_Baseboard_RCD: C117 C118 C119 C120 C121 C122 C123 C124 C125 C126 C127 C128 C129 C130 C131 C132 C133 C134 C138 C139 C140 C141 C800 D45 D46 J16 J17 R127 R129 R130 R131 R133 R134 R135 R136 R137 R138 R139 R140 R141 R142 R143 R144 R145 R146 R147 R148 R151 R152 R153 R154 R155 R156 R157 U21 U22 U23 U24 U26 U27 U28 U29 U30
component class AC_L2_Baseboard_RCD_MCU: C146 C147 C148 C149 C150 C151 C152 C153 C154 C155 P1 R99 R175 R178 R179 R180 R184 R187 R188 R189 R190 R191 U32 Y1
component class AC_L2_Baseboard_PlugLock: C114 C115 C116 F4 J15 R125 R126 U20
component class AC_L2_Baseboard_Pilot_Wire_ADC: C99 C100 C108 C109 C110 C111 D35 J4 L18 NT3 Q9 R85 R86 R87 R88 R89 R90 R91 R92 R93 R94 R95 R96 R97 TP24 TP25 TP26 U18 U19
component class AC_L2_Baseboard_HPGP_ZC: C95 C96 C97 C98 D34 R29 R82 R83 R84 U14
component class AC_L2_Baseboard_Hardware: !PCB FID1 FID2 FID3 H1 H2 H3 H4 H5 H6 LBL1 LOGO1 Logo2 Logo3 Logo4 LOGO5
component class AC_L2_Baseboard_Connectors: J2 J3

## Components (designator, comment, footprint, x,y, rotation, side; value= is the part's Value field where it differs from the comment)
C1_P "GRM21A5C2E680JW01D" 0805_HV 3635,2409 r180 bottom value=68pF
C2_P "DE1E3KX332MN4AP01F" KX_1000x700 2810,1364 r180 top value=3300pF
C3_P "DE1E3KX332MN4AP01F" KX_1000x700 3285,1364 r180 top value=3300pF
C4_P "860010473007" Chemi-Con_630X1100 3835,2459 r270 top value=100uF
C5_P "885012109015" 1210_270 3560,2484 r180 top value=22uF
C6_P "C1812C104KDRAC7800" 1812_254 2485,2039 r90 bottom value=0.1uF
C7_P "C1812C104KDRAC7800" 1812_254 2660,2039 r90 bottom value=0.1uF
C8_P "885342207008" 0805_HV 1660,2039 r90 bottom value=1000pF
C9_P "890493425009CS" B32672P_1800x850x1450 1010,2214 r270 top value=0.1uF
C10_P "885012109015" 1210_270 3560,2234 r0 top value=22uF
C11_P "GRM21A5C2E680JW01D" 0805_HV 3635,2109 r180 bottom value=68pF
C12_P "860010473007" Chemi-Con_630X1100 3835,2184 r270 top value=100uF
C13_P "860021380017" HW_1600x2500 2245,1234 r270 top value=68uF
C14_P "860021380017" HW_1600x2500 1570,1234 r270 top value=68uF
C15_P "890493425009CS" B32672P_1800x850x1450 1010,1414 r270 top value=0.1uF
C16_P "860021380017" HW_1600x2500 1570,537.36 r270 top value=68uF
C17_P "860021380017" HW_1600x2500 2245,540 r270 top value=68uF
C18_P "885012206095" 0603 3735,1549 r90 bottom value=0.1uF
C19_P "GRM188Z71C225KE43" 0603S 3665,1655 r180 bottom value=2.2uF
C20_P "890493425009CS" B32672P_1800x850x1450 1010,639 r270 top value=0.1uF
C21_P "885012109015" 1210_270 3160,1709 r180 bottom value=22uF
C22_P "885012109015" 1210_270 3160,1834 r180 bottom value=22uF
C23_P "885012109015" 1210_270 3160,1964 r180 bottom value=22uF
C24_P "885012109015" 1210_270 3160,2089 r180 bottom value=22uF
C25_P "860040475009" Chemi-Con_1000x2000 3825,1799 r270 top value=680uF
C26_P "860040475009" Chemi-Con_1000x2000 4250,1799 r270 top value=680uF
C27_P "GRM21A5C2E101JW01D" 0805_HV 3445,1524 r270 bottom value=100pF
C28_P "885012206085" 0603 3335,1204 r0 bottom value=2200pF
C29_P "885012206095" 0603 3235,1234 r90 bottom value=0.1uF
C30_P "885012108022" 1206_190 2485,1664 r180 bottom value=10uF
C31_P "885012107018" 0805_HV 3635,1239 r180 top value=4.7uF
C32_P "885012206095" 0603 2040,2099 r180 top value=0.1uF
C33_P "885012108022" 1206 4645,2419 r180 bottom value=10uF
C34_P "885012006057" 0603 1910,1989 r270 top value=100pF
C35_P "885012206093" 0603 2040,1700 r0 top value=0.047uF
C36_P "885012006057" 0603 5113.7,2089 r90 bottom value=100pF
C37_P "885012206095" 0603 5013.7,2114 r0 bottom value=0.1uF
C38_P "PHVL-3R9V255-R" FP-PHVL-3R9V255-R_RADIAL-MFG 4910,2414 r180 top value=2.5F
C39_P "PHVL-3R9V255-R" FP-PHVL-3R9V255-R_RADIAL-MFG 4910,1939 r180 top value=2.5F
C40_P "885012206095" 0603 4838.7,2064 r270 bottom value=0.1uF
C41_P "885012206095" 0603 4913.7,2064 r270 bottom value=0.1uF
C42_P "885012206095" 0603 4763.7,2064 r270 bottom value=0.1uF
C43_P "885012109015" 1210_270 3035,919 r180 top value=22uF
C44_P "885012108022" 1206 4280,2069 r0 top value=10uF
C45_P "885012006050" 0603 3306,884 r0 top value=6.8pF
C46_P "885012206089" 0603 4135,2414 r180 bottom value=0.01uF
C47_P "885012108022" 1206 4155,2234 r270 top value=10uF
C48_P "885012206076" 0603 4410,2539 r0 bottom value=1uF
C49_P "885012206048" 0603 3556,859 r180 top value=0.22uF
C50_P "885012208019" 1206_190 3060,444 r270 top value=22uF
C51_P "885012206095" 0603 3166,639 r90 top value=0.1uF
C52_P "885012006092" 0603 3556,649 r0 top value=5.6pF
C53_P "885012108022" 1206 4410,2234 r90 top value=10uF
C54_P "885012109015" 1210_270 3186,444 r270 top value=22uF
C55_P "885012206095" 0603 3206,739 r180 top value=0.1uF
C56_P "885012206089" 0603 3411,919 r270 top value=0.01uF
C57_P "885012206087" 0603 3556,929 r0 top value=4700pF
C58_P "885012206089" 0603 4450,2359 r270 bottom value=0.01uF
C59_P "885012206076" 0603 4160,2524 r90 bottom value=1uF
C60_P "885012206089" 0603 4280,2154 r180 top value=0.01uF
C61_P "885012108022" 1206 4280,2404 r180 top value=10uF
C62_P "885012206087" 0603 3185,544 r90 bottom value=4700pF
C63_P "885012206095" 0603 4010,523.06 r270 top value=0.1uF
C64_P "885012109015" 1210_270 3880,444 r0 bottom value=22uF
C65_P "885012206095" 0603 3885,414 r0 top value=0.1uF
C66_P "885012208019" 1206_190 4240,554 r180 bottom value=22uF
C67_P "885012208019" 1206_190 4240,434 r180 bottom value=22uF
C68_P "885012208019" 1206_190 4240,654 r180 bottom value=22uF
C69_P "885012206076" 0603 4760,414 r270 top value=1uF
C70_P "885012206095" 0603 4685,414 r270 top value=0.1uF
C71_P "885012206089" 0603 4610,414 r90 top value=0.01uF
C72_P "885012206076" 0603 4535,984 r90 top value=1uF
C73_P "885012206076" 0603 4750,844 r90 top value=1uF
C74_P "885012109015" 1210_270 4885,864 r90 bottom value=22uF
C75_P "885012206089" 0603 3675,519 r90 top value=0.01uF
C76_P "885012206085" 0603 4610,984 r90 top value=2200pF
C77_P "885012206111" 0603 4750,984 r90 top value=3300pF
C78_P "GRM188R61A106KE69D" 0603 4860,574 r270 top value=10uF
C79_P "885012109015" 1210_270 4500,1584 r270 top value=22uF
C80_P "885012109015" 1210_270 4635,1584 r270 top value=22uF
C81_P "885012206076" 0603 4640,574 r270 top value=1uF
C82_P "885012206095" 0603 4610,1389 r90 top value=0.1uF
C83_P "885012109015" 1210_270 5050,1404 r270 top value=22uF
C84_P "885012109015" 1210_270 4915,1404 r270 top value=22uF
C85_P "885012206095" 0603 4010,1001.6 r270 top value=0.1uF
C86_P "885012006050" 0603 5095,1239 r270 top value=6.8pF
C87_P "885012109015" 1210_270 3885,920.3 r0 bottom value=22uF
C88_P "885012206095" 0603 3885,900.61 r0 top value=0.1uF
C89_P "885012208019" 1206_190 4260,1026.6 r180 bottom value=22uF
C90_P "885012208019" 1206_190 4260,901.6 r180 bottom value=22uF
C91_P "885012206081" 0603 4765,1250 r180 top value=470pF
C92_P "885012206095" 0603 4630,1249 r0 top value=0.1uF
C93_P "885012206089" 0603 4730,1149 r270 top value=0.01uF
C94_P "885012206089" 0603 3685,989 r90 top value=0.01uF
C95 "GRM31BR73A222KW01L" 1206 465,3007.09 r90 top value=2200pF
C96 "GCM188R71E105KA64D" 0603 1790,2955 r270 top value=1uF
C97 "GRM188R71E102KA01D" 0603 1685,2955 r270 top value=1000pF
C98 "CC0603KRX7R7BB224" FP-CC0603KRX7R7BB224_0603-MFG 1615,2955 r90 top value=220nF
C99 "GRM188R71E104KA01D" 0603 6130,2226.5 r270 top value=0.1uF
C100 "GRM188R71E104KA01D" 0603 6430,2305 r0 top value=0.1uF
C108 "CGJ3E1X7R1E105K080AC" 0603 5848.5,955 r0 top value=1uF
C109 "GRM188R71E104KA01D" 0603 5850,1035 r0 top value=0.1uF
C110 "CGA3E2NP01H470J080AA" 0603 5960,1450 r0 top value=47pF
C111 "CGA3E2NP01H470J080AA" 0603 5985,1035 r180 top value=47pF
C114 "CC1210KKX7R8BB226" 1210_270 6384.33,6224.88 r270 top value=22uF
C115 "CC1210KKX7R8BB226" 1210_270 6249.76,6224.88 r270 top value=22uF
C116 "TMK105B7104MV-FR" 0402S 6155,6280 r270 top value=0.1uF
C117 "16V 100nF" FP-GRT033-0_03-IPC_B 4659.81,6106.96 r180 top
C118 "16V 100nF" FP-GRT033-0_03-IPC_B 4769.57,5623.4 r180 top
C119 "16V 100nF" FP-GRT033-0_03-IPC_B 4794.59,5377.4 r180 top
C120 "16V 100nF" FP-GRT033-0_03-IPC_B 4781.56,4993.98 r180 top
C121 "16V 100nF" FP-GRT033-0_03-IPC_B 4768.19,5933.04 r180 top
C122 "16V 100nF" FP-GRT033-0_03-IPC_B 4529.59,5584.4 r0 top
C123 "16V 100nF" FP-GRT033-0_03-IPC_B 4539.59,5337.4 r0 top
C124 "16V 100nF" FP-GRT033-0_03-IPC_B 4608.56,4897.98 r0 top
C125 "16V 100nF" FP-GRT033-0_03-IPC_B 5232.96,5737.44 r90 top
C126 "16V 100nF" FP-GRT033-0_03-IPC_B 5491.04,5882.56 r270 top
C127 "16V 100nF" FP-GRT033-0_03-IPC_B 5113.58,6229.96 r180 top
C128 "16V 100nF" FP-GRT033-0_03-IPC_B 5679.56,5797.96 r180 top
C129 "35V 1uF" FP-GRM155-0_1-MFG 4540.81,5934.96 r180 top
C130 "35V 1uF" FP-GRM155-0_1-MFG 4654.04,5737.81 r0 top
C131 "50V 47pF" FP-C0603-030-0_03-MFG 4700.07,5280.96 r0 top
C132 "35V 2.2uF" FP-GRM155-0_2-MFG 4635.56,6164.96 r180 top
C133 "C1206C395K4PACTU" 1206L 4653.26,5838.79 r0 top value=3.9uF
C134 "35V 1uF" FP-GRM155-0_1-MFG 4475.19,6055.04 r180 top
C138 "CC1210KKX7R8BB226" 1210_270 5535.56,6104.96 r0 top value=22uF
C139 "CC1210KKX7R8BB226" 1210_270 5535.56,6244.96 r0 top value=22uF
C140 "TMK105B7104MV-FR" 0402S 5465.56,6004.96 r0 top value=0.1uF
C141 "16V 100nF" FP-C0201-AB-MFG 5521.56,5696.96 r90 top value="10,000 pF"
C146 "GRM155R61A474KE15D" 0402 5427.41,4729.72 r0 top value=0.47uF
C147 "C1608NP01H060D080AA" FP-C1608-080-0_1-IPC_B 5090.56,5369.96 r270 top
C148 "C1608NP01H060D080AA" FP-C1608-080-0_1-IPC_B 5265.56,5369.96 r270 top
C149 "6.3V 10uF" FP-GRM155-0_2-MFG 5296.03,4517.4 r0 top
C150 "6.3V 0.1uF" CAPC1005X56X25NL10T15 5296.03,4572.4 r180 top
C151 "C0603C103K4RACTU" 0603 5497.82,5264.41 r90 top value=0.01uF
C152 "6.3V 10uF" FP-GRM155-0_2-MFG 5417.41,4857.4 r0 top
C153 "6.3V 0.1uF" CAPC1005X56X25NL10T15 5417.41,4802.4 r180 top
C154 "6.3V 10uF" FP-GRM155-0_2-MFG 5160.56,5039.96 r180 top
C155 "6.3V 0.1uF" CAPC1005X56X25NL10T15 5160.56,4984.96 r0 top
C156 "CGA3E2X7R2A102K080AA" 0603 4251.3,3090 r90 top value=1000pF
C157 "C0603C104K4RACTU" 0603 4850,3155 r270 top value=0.1uF
C158 "CGA3E2X7R2A102K080AA" 0603 4239.45,3445 r90 top value=1000pF
C159 "Q07E1D471KN0B0S0N0" FP-Q07E1D471KN0B0S0N0_RADIAL-MFG 4645,3500 r180 top value=470pF
C160 "CC1210KKX7R8BB226" 1210_270 1160,3525 r270 top value=22uF
C161 "CC1210KKX7R8BB226" 1210_270 1295,3525 r270 top value=22uF
C162 "TMK105B7104MV-FR" 0402S 1395,3560 r270 top value=0.1uF
C163 "CGA3E2X7R2A102K080AA" 0603 4248.54,3792.85 r90 top value=1000pF
C164 "C0603C104K4RACTU" 0603 4817.44,3883.01 r270 top value=0.1uF
C165 "CGA3E2X7R2A102K080AA" 0603 4240,4167.3 r90 top value=1000pF
C166 "Q07E1D471KN0B0S0N0" FP-Q07E1D471KN0B0S0N0_RADIAL-MFG 4625,4245 r180 top value=470pF
C167 "TMK105B7104MV-FR" 0402S 1826.47,3445.04 r90 top value=0.1uF
C200_P "C0603C221J5GACTU" 0603 2040,1895 r0 top value=220pF
C800 "16V 100nF" FP-GRT033-0_03-IPC_B 5500,5778 r180 top
D1_P "MBR0540T1G" SOD-123 4035,2264 r90 top
D2_P "SS1200-LTP" SMA 3518.07,2537.15 r180 bottom
D3_P "MBR0540T1G" SOD-123 3935,2484 r90 bottom
D4_P "TBS22M-TP" TBS4 1135,2214 r180 bottom
D5_P "MBR0540T1G" SOD-123 4035,2064 r90 top
D6_P "SMCJ130A-TR" SMC 1485,1989 r270 bottom value=130V
D7_P "SS1200-LTP" SMA 3535,2234 r0 bottom
D8_P "MBR0540T1G" SOD-123 3935,2259 r90 bottom
D9_P "US1M-13-F" SMA 1510,2289 r0 bottom
D10_P "TBS22M-TP" TBS4 1135,614 r180 bottom
D11_P "150120GS75000" WL_SMCW_RED_1206 4085,1489 r0 top value=Green
D12_P "US1G-13-F" SMA 2660,1739 r90 bottom
D13_P "BAT54SLT1G" SOT-23 3635,1439 r0 top
D14_P "BAS20HT1G" SOD-323 1915,1584 r0 bottom
D15_P "SS1200-LTP" SMA 4735,2554 r180 bottom
D16_P "BZX384C43-E3-08" SOD-323 1915,1654 r0 bottom value=43V
D17_P "BAS20HT1G" SOD-323 5110,2295.5 r90 bottom
D18_P "BAS20HT1G" SOD-323 4660,1939 r180 bottom
D19_P "150120AS75000" WL_SMCW_RED_1206 5260,1589 r90 top value=Amber
D20_P "SS2040FL_R1_00001" SOD-123FL 3186,879 r270 top
D21_P "SD103AWS-TP" SOD-323 4140,2149 r90 bottom
D22_P "SS2040FL_R1_00001" SOD-123FL 3370,564 r180 top
D23_P "BAS20HT1G" SOD-323 3210,2539 r90 bottom
D24_P "SD103AWS-TP" SOD-323 4425,2244 r180 bottom
D25_P "SZMM3Z16VST1G" SOD-323 3386,544 r90 bottom value=16V
D26_P "BZT52C5V1S-7-F" SOD-323 5040,389 r0 top value=5.1V
D27_P "150120RS75000" WL_SMCW_RED_1206 5010,544 r180 top value=Red
D28_P "SMAJ15CA" SMA_Bi 5135,864.33 r270 bottom value=15V
D29_P "BAS20HT1G" SOD-323 5010,664 r0 bottom
D30_P "150120GS75000" WL_SMCW_RED_1206 4355,270 r0 top value=Green
D31_P "150120RS75000" WL_SMCW_RED_1206 5010,644 r180 top value=Red
D32_P "MBRS2040LT3G" SMB 5035,1589 r180 top value=40V
D33_P "150120GS75000" WL_SMCW_RED_1206 4360,754 r0 top value=Green
D34 "US1M-13-F" SMA 975,2980 r270 top value=1000V
D35 "AQ4023-01FTG-C" FP-AQ4023-01FTG-C_SOD323-MFG 6255,1320 r180 top
D45 "1N914BWT" FP-502-01-MFG 4685.9,5226.4 r180 top value=4pF
D46 "1N914BWT" FP-502-01-MFG 4712.56,5133.96 r90 top value=4pF
D47 "MDB6S" MICRODIP_4 3964.57,3092.3 r180 top value=600V
D48 "MDB6S" MICRODIP_4 3955,3445 r180 top value=600V
D49 "MDB6S" MICRODIP_4 3945,3800 r180 top value=600V
D50 "MDB6S" MICRODIP_4 3945,4165 r180 top value=600V
D51 "150060GS75000" WL-SMCW_GREEN 1950,3615 r0 top value=Green
D52 "150060GS75000" WL-SMCW_GREEN 5332.17,3221.87 r0 top value=Green
D53 "150060GS75000" WL-SMCW_GREEN 5323.5,3430 r0 top value=Green
D54 "150060GS75000" WL-SMCW_GREEN 5280.98,3935.31 r0 top value=Green
D55 "150060GS75000" WL-SMCW_GREEN 5275,4115.31 r0 top value=Green
D200_P "MM3Z7V5ST1G" SOD-323 3750,498.31 r90 top value=7.5V
D201_P "MM3Z7V5ST1G" SOD-323 3765,962.31 r90 top value=7.5V
D800 "UFM15PL-TP" SOD-123FL 3974,3252 r0 top value=600V
D801 "UFM15PL-TP" SOD-123FL 3968,3613 r0 top value=600V
D802 "UFM15PL-TP" SOD-123FL 3950,3971 r0 top value=600V
D803 "UFM15PL-TP" SOD-123FL 3952,4337 r0 top value=600V
F1_P "0443001.DR" FUSE_0443 360,2089 r90 bottom value=1A
F2_P "0443001.DR" FUSE_0443 360,1364 r90 bottom value=1A
F3_P "0443001.DR" FUSE_0443 360,664 r90 bottom value=1A
F4 "044001.5WR" 1206 6390,5880 r270 top
F5 "044001.5WR" 1206 1040,3520 r270 top
FID1 "Fiducial" Fiducial10-20 340,6620 r90 top
FID2 "Fiducial" Fiducial10-20 340,30 r90 top
FID3 "Fiducial" Fiducial10-20 6455,33.5 r90 top
H1 "NY PMS 440 0025 PH" "NY PMS 440 0025 PH" 6800,6595 r0 top
H2 "NY PMS 440 0025 PH" "NY PMS 440 0025 PH" 35,6620 r0 top
H3 "NY PMS 440 0025 PH" "NY PMS 440 0025 PH" -5,20 r0 top
H4 "NY PMS 440 0025 PH" "NY PMS 440 0025 PH" 6845,40 r0 top
H5 "NY PMS 440 0025 PH" "NY PMS 440 0025 PH" 1722.5,6620 r0 top
H6 "NY PMS 440 0025 PH" "NY PMS 440 0025 PH" 3410,6620 r0 top
J1_P "691214110002" Wurth_691214110002 5025,869 r90 top
J2 "FTSH-120-01-L-D" FP-FTSH-120-01-L-D_HDR40-MFG 6622,3525 r270 top
J3 "61301421121" Wurth_61301421121 6601,4845 r180 top
J4 "691 101 710 003" Wurth_691101710003 6730,1895 r90 top
J15 "691 101 710 002" Wurth_691101710002 6075,6575 r180 top
J16 "691137710002" 691137710002 4647.13,6574.8 r180 top
J17 "691137710002" 691137710002 5387.13,6574.8 r180 top
J19 "74650073R" Wurth_WP-THRBU 455.55,6064.45 r0 top
J20 "74650073R" Wurth_WP-THRBU 2850.55,6064.45 r0 top
J21 "74650073R" Wurth_WP-THRBU 455.55,5527.97 r0 top
J22 "74650073R" Wurth_WP-THRBU 2850.55,5531.12 r0 top
J23 "74650073R" Wurth_WP-THRBU 455.55,4991.48 r0 top
J24 "74650073R" Wurth_WP-THRBU 2850.55,4997.78 r0 top
J25 "74650073R" Wurth_WP-THRBU 455.55,4455 r0 top
J26 "74650073R" Wurth_WP-THRBU 2850.55,4464.45 r0 top
K1 "AHER4191" FP-AHER4191_PTH_RELAY_35MM0_58MM0-MFG 1640,5015 r90 top
L1_P "74279205" 0805_HV 3710,2534 r90 bottom value="1 KOhm @ 100 MHz"
L2_P "7447480151" WE-TI_1014 585,2114 r270 top value=150uH
L3_P "74279205" 0805_HV 3805,2054 r0 bottom value="1 KOhm @ 100 MHz"
L4_P "7447480151" WE-TI_1014 560,1364 r270 top value=150uH
L5_P "7446121007" Wurth_7446120047 1485,2139 r0 top value=6.8mH
L6_P "7447480151" WE-TI_1014 560,639 r270 top value=150uH
L7_P "DNP" WE-PD2-S 3995,1804 r90 bottom
L8_P "744042100" WE-TPC-M1 3005,724 r0 top value=10uH
L9_P "74279221281" 1206 3685,339 r180 bottom value="280 ohm @ 100 MHz"
L10_P "744042100" WE-TPC-M1 3386,397 r180 top value=10uH
L11_P "74279221601" 1206_180 3685,664 r270 bottom value="600 ohm @ 100 MHz"
L12_P "74279221281" 1206 4500,579 r0 top value="280 ohm @ 100 MHz"
L13_P "744311470" WE-HC4 4235,498.06 r0 top value=4.7uH
L14_P "74279221281" 1206 5185,1244 r270 top value="280 ohm @ 100 MHz"
L15_P "XEL4030-332MEB" XEL4030_310 4800,1589 r270 top value=3.3uH
L16_P "74279221601" 1206_180 3685,859 r90 bottom value="600 ohm @ 100 MHz"
L17_P "744311470" WE-HC4 4235,976.6 r0 top value=4.7uH
L18 "7447779222" WE-PD_7345_PlasticBase 6300,1570 r270 top value=220uH
LBL1 "THT-14-423-10" Label_650x200 3870,5915 r90 bottom
LOGO1 "DANGER HIGH VOLTAGE" IEC_HighVoltage_Medium 495,3755 r270 top
Logo2 "CE Mark" CE_Mark_5mm 3580,5725 r180 bottom
Logo3 "FCC disclaimer" FCC_disclaimer 7460.1,5310 r90 bottom
Logo4 "WEEE logo" WEEE_Minimum 3575,6105 r180 bottom
LOGO5 "DANGER HIGH VOLTAGE" IEC_HighVoltage_Medium 665,3185 r90 bottom
NT1_P "Net-Tie" Net-Tie_10mil 3294.21,774.5 r180 top net-tie
NT2_P "Net-Tie" Net-Tie_10mil 4750,1350 r90 top net-tie
NT3 "Net-Tie" Net-Tie_0805_HV_NoOverlay 6030,2225 r270 top net-tie
P1 "87831-1420" MOLEX-87831-1420_V 4260.63,4935.78 r270 top
Q1_P "BSC500N20NS3G" FP-BSC220N20NSFDATMA1_TSON-8-MFG 3616.54,1844.47 r180 bottom
Q2_P "IPD95R2K0P7ATMA1" FP-IPD95R2K0P7ATMA1_DPAK-MFG 2020,2278.54 r180 bottom
Q3_P "IRFIZ24G" TO-220FP 5445,2445 r90 bottom value=60V
Q4_P "MMBT3904LT1G" SOT-23 5010,2245.5 r270 bottom value="40 V"
Q5_P "BSS138" SOT-23 4660,1764 r0 bottom
Q6_P "BSS138" SOT-23 3511,569 r0 bottom
Q7_P "BSS138" SOT-23 4060,373.06 r0 bottom
Q8_P "BSS138" SOT-23 4010,789 r0 top
Q9 "BSS138" SOT-23 6326.04,1025 r0 top value=50V
Q10 "BC848CLT1G" SOT-23 1781.47,3625.04 r0 top value="30 V"
Q11 "BC848CLT1G" SOT-23 5162.17,3226.87 r0 top value="30 V"
Q12 "BC848CLT1G" SOT-23 5160,3430 r0 top value="30 V"
Q13 "BC848CLT1G" SOT-23 5109.68,3925.61 r0 top value="30 V"
Q14 "BC848CLT1G" SOT-23 5105.2,4133.01 r0 top value="30 V"
R1_P "ERJ-6GEYJ102V" 0805_HV 3460,2409 r0 bottom value=1.0k
R2_P "CRCW1206470KJNEA" 1206 860,2464 r90 bottom value=470k
R3_P "CRCW080510K0FKEA" 0805_HV 510,2114 r270 bottom value=10.0k
R4_P "CRCW1206470KJNEA" 1206 1760,2039 r270 bottom value=470k
R5_P "CRCW12061M00JNEA" 1206 1760,1189 r90 bottom value=1.0Meg
R6_P "ERJ-6GEYJ102V" 0805_HV 3460,2109 r0 bottom value=1.0k
R7_P "CRCW1206470KJNEA" 1206 860,1964 r90 bottom value=470k
R8_P "CRCW12061M00JNEA" 1206 1760,989 r90 bottom value=1.0Meg
R9_P "CRCW1206470KJNEA" 1206 860,1614 r90 bottom value=470k
R10_P "CRCW080510K0FKEA" 0805_HV 485,1364 r270 bottom value=10.0k
R11_P "CRCW120610R0JNEA" 1206 1760,2289 r180 bottom value=10
R12_P "CRCW1206470KJNEA" 1206 860,1189 r90 bottom value=470k
R13_P "CRCW12061M00JNEA" 1206 2010,989 r270 bottom value=1.0Meg
R14_P "RC1206JR-070RL" 1206 4445,989 r270 top value=0
R15_P "CRCW080510K0FKEA" 0805_HV 685,639 r270 bottom value=10.0k
R16_P "CRCW1206470KJNEA" 1206 860,839 r90 bottom value=470k
R17_P "CRCW12061M00JNEA" 1206 2010,1189 r270 bottom value=1.0Meg
R19_P "CRCW1206470KJNEA" 1206 860,389 r90 bottom value=470k
R20_P "RC0603FR-074K7L" 0603 4085,1489 r0 bottom value=4.70k
R21_P "CRCW060349R9FKEA" 0603 3470,1204 r180 bottom value=49.9
R22_P "CRCW12061K00JNEA" 1206 3415,1709 r90 bottom value=1.0k
R23_P "CRCW080520R0JNEA" 0805_HV 2460,1814 r180 bottom value=20
R24_P "CRCW06032K49FKEA" 0603 3280,1514 r270 bottom value=2.49k
R25_P "RC0603FR-076K81L" 0603 3350,1514 r270 bottom value=6.81k
R26_P "ERJ-6ENF6042V" 0805_HV 2135,1664 r0 bottom value=60.4k
R27_P "RC0603FR-0738K3L" 0603 3470,1274 r0 bottom value=38.3k
R28_P "ERJ-6ENF6042V" 0805_HV 1885,1789 r180 top value=60.4k
R29 "CRCW1206390KJNEA" 1206 635,3005 r90 top value=390k
R29_P "RC0603FR-0710KL" 0603 3335,1274 r0 bottom value=10.0k
R30_P "CRCW0603100KFKEA" 0603 3635,1339 r0 top value=100k
R31_P "RC0603FR-0733K2L" 0603 1885,1889 r0 top value=33.2k
R32_P "RC0603FR-0710KL" 0603 3335,1344 r180 bottom value=10.0k
R33_P "CRCW06031K00FKEA" 0603 1840,2059 r90 top value=1.00k
R34_P "RC0603FR-0710KL" 0603 5325,2410 r270 bottom value=10.0k
R35_P "CSRN2010FKR500" 2010 1910,1839 r90 bottom value=0.5
R36_P "RC0603FR-074K7L" 0603 4660,1864 r180 bottom value=4.70k
R37_P "RC0603FR-0733KL" 0603 2040,1765 r180 top value=33.0k
R38_P "CRCW06034R99FKEA" 0603 5010,2350 r180 bottom value=4.99
R39_P "RC0603FR-0710KL" 0603 5185,2270.5 r270 bottom value=10.0k
R40_P "RC0603FR-074K7L" 0603 2040,1830 r0 top value=4.70k
R41_P "RC0603FR-0710KL" 0603 5013.7,2039 r180 bottom value=10.0k
R42_P "RC0603FR-0711K8L" 0603 4660,2264 r270 bottom value=11.8k
R43_P "CRCW06031K00FKEA" 0603 4810,2264 r90 bottom value=1.00k
R44_P "CRCW06031K00FKEA" 0603 4735,2264 r90 bottom value=1.00k
R45_P "RC0603FR-074K7L" 0603 5260,2270.5 r270 bottom value=4.70k
R46_P "RC0603FR-0791KL" 0603 4135,2349 r0 bottom value=91.0k
R47_P "CRCW0603976KFKEA" 0603 3306,954 r180 top value=976k
R48_P "CRCW060393K1FKEA" 0603 3376,1024 r0 top value=93.1k
R49_P "RC0603FR-0710KL" 0603 4134,2279 r180 bottom value=10.0k
R50_P "RC0603FR-0768KL" 0603 3556,789 r180 top value=68.0k
R51_P "RC0603FR-07787KL" 0603 3556,719 r180 top value=787k
R52_P "CRCW0603100RFKEA" 0603 3236,639 r270 top value=100
R53_P "RC0603FR-0710KL" 0603 3556,579 r0 top value=10.0k
R54_P "CRCW0603100KFKEA" 0603 4380,2359 r270 bottom value=100k
R55_P "RC0603FR-0710KL" 0603 4410,2464 r180 bottom value=10.0k
R56_P "CRCW0805100RFKEA" 0805_HV 3210,2364 r270 bottom value=100
R57_P "CRCW0603100KFKEA" 0603 3311,544 r270 bottom value=100k
R58_P "RC0603FR-074K7L" 0603 5030,459 r0 top value=4.70k
R60_P "CRCW0603475KFKEA" 0603 4820,784 r90 top value=475k
R61_P "CRCW0603100KFKEA" 0603S 4015,624 r0 top value=100k
R62_P "RC0603FR-0733K2L" 0603 4015,689 r0 top value=33.2k
R63_P "RMCF0603FT11K0" 0603 4585,734 r180 top value=11.0k
R64_P "RC0603FR-074K7L" 0603 4255,324 r0 bottom value=4.70k
R65_P "RC0603FR-0710KL" 0603 3880,689 r0 top value=10.0k
R66_P "CRCW0603750RFKEA" 0603 4680,984 r270 top value=750
R67_P "RC0603FR-0747KL" 0603 4720,734 r180 top value=47.0k
R68_P "RC0603FR-074K7L" 0603 5010,589 r0 bottom value=4.70k
R69_P "CRCW0603100RFKEA" 0603 4535,1389 r90 top value=100
R70_P "RC0603FR-0710KL" 0603 4460,1389 r90 top value=10.0k
R71_P "RC0603FR-07100KL" 0603 4955,1239 r90 top value=100k
R72_P "RC0603FR-07510KL" 0603 5025,1239 r90 top value=510k
R74_P "CRCW0603100KFKEA" 0603 4005,1125 r0 top value=100k
R75_P "RC0603FR-0747KL" 0603 4795,1149 r90 top value=47.0k
R76_P "RC0603FR-0754K9L" 0603 4020,1191.4 r0 top value=54.9k
R77_P "RC0603FR-0710KL" 0603 4925,1119 r0 top value=10.0k
R78_P "RT0603DRE0746K4L" 0603 4885,1239 r90 top value=46.4k
R79_P "RC0603FR-074K7L" 0603 4160,764 r0 top value=4.70k
R80_P "RC0603FR-0710KL" 0603 3885,1189 r0 top value=10.0k
R82 "CRCW0603100RJNEA" 0603 1790,3070 r180 top value=100
R83 "CRCW1206390KJNEA" 1206 760,3005 r270 top value=390k
R84 "RC0603JR-0739KL" 0603 1650,3070 r0 top value=39k
R85 "CRCW0603220RJNEA" 0603 6100,1575 r270 top value=220
R86 "RC0603FR-07200KL" 0603 6310,2473.5 r90 top value=200k
R87 "RC0603JR-071KL" 0603 6400,2160 r270 top value=1.0k
R88 "RC0603FR-07200KL" 0603 6430,2375 r180 top value=200k
R89 "RC0603FR-07200KL" 0603 6358.35,2025 r0 top value=200k
R90 "RC0603JR-0756KL" 0603 6358.35,1945 r0 top value=56k
R91 "RC0603FR-0766K5L" 0603 6180,2025 r0 top value=66.5k
R92 "RC0603FR-071KL" 0603 5930,1555 r270 top value=1.00k
R93 "CRCW0805150RFKEA" 0805_HV 6498.29,875 r0 top value=150
R94 "RC0603FR-07200KL" 0603 6056.3,850 r0 top value=200k
R95 "RC0603FR-071KL" 0603 5990,955 r0 top value=1.00k
R96 "RC0603FR-07200KL" 0603 5916.3,850 r0 top value=200k
R97 "CRCW0805330RFKEAC" 0805_HV 6328.29,875 r0 top value=330
R99 "0 ohm" RESC1005X40X25NL05T10 5380.56,5039.96 r270 top
R125 "RCS06030000Z0EA" 0603 6080,5995 r270 top value=0
R126 "RC0603JR-0710KL" 0603 6155,5995 r90 top value=10k
R127 "100k" RESC0603X28X15LL05T05 4827.59,5704.58 r90 top
R129 "56k" FP-RG1005-IPC_B 5137.56,5665.26 r0 top
R130 "100k" RESC0603X28X15LL05T05 5742.56,5691.96 r90 top
R131 "100k" RESC0603X28X15LL05T05 4827.59,5635.96 r90 top
R133 "10k" RESC0603X28X15LL05T05 5052.56,5670.26 r0 top
R134 "100k" RESC0603X28X15LL05T05 5742.56,5631.96 r90 top
R135 "1.3k" RESC0603X28X15LL05T05 4712.81,5749.96 r270 top
R136 "1.3k" RESC0603X28X15LL05T05 4720.56,6105.96 r270 top
R137 "1.0k" RESC0603X28X15NL05T05 4637.56,5148.96 r270 top
R138 "1.0k" RESC0603X28X15NL05T05 4578.04,5016.56 r270 top
R139 "1.3k" RESC0603X28X15LL05T05 4765.56,6176.85 r270 top
R140 "750" RESC0603X28X15LL05T05 4765.11,6105.75 r270 top
R141 "1.3k" RESC0603X28X15LL05T05 4537.04,5886.81 r0 top
R142 "750" RESC0603X28X15LL05T05 4595.81,5748.96 r270 top
R143 "ERJ-1TYJ102U" 2512 4647.84,6315.12 r0 top value=1.0k
R144 "AC0402FR-070RL" FP-AC0402-0_37-IPC_B 4717.59,5483.4 r0 top
R145 "1.3k" RESC0603X28X15LL05T05 4530.56,6176.85 r270 top
R146 "750" RESC0603X28X15LL05T05 4530.56,6093.74 r270 top
R147 "1.0k" RESC0603X28X15NL05T05 4779.76,5106.96 r180 top
R148 "1.3k" RESC0603X28X15LL05T05 4471.74,6105 r180 top
R151 "1.0k" RESC0603X28X15NL05T05 5435.56,6374.96 r0 top
R152 "1.0k" RESC0603X28X15NL05T05 5350.56,6374.96 r180 top
R153 "CRCW12063R00JNEA" FP-CRCW1206-e3-IPC_A 5275.56,6084.96 r270 top
R154 "1.0k" RESC0603X28X15NL05T05 5286.56,5736.96 r90 top
R155 "499k" RESC0603X28X15NL05T05 5109.15,5921.56 r0 top
R156 "1M" RESC0603X28X15LL05T05 5172.56,5922.96 r0 top
R157 "100k" RESC0603X28X15LL05T05 5532.56,5630.96 r180 top
R175 "0 ohm" RESC1005X40X25NL05T10 5015.68,4889.72 r0 top
R178 "0 ohm" RESC1005X40X25NL05T10 5015.68,4834.72 r0 top
R179 "0 ohm" RESC1005X40X25NL05T10 4899,4803 r0 top
R180 "0 ohm" RESC1005X40X25NL05T10 4897,4749 r0 top
R184 "0 ohm" RESC1005X40X25NL05T10 5171.03,4540.67 r90 top
R187 "0 ohm" RESC1005X40X25NL05T10 5226.03,4537.4 r90 top
R188 "ERA-3ARB102V" FP-ERA3A-IPC_B 5595.56,5134.96 r270 top
R189 "0 ohm" RESC1005X40X25NL05T10 5325.56,5039.96 r270 top
R190 "0 ohm" RESC1005X40X25NL05T10 5230.56,5039.96 r270 top
R191 "RC0603FR-0747KL" 0603 5500.56,5134.96 r270 top value=47.0k
R192 "CRCW120630K0JNEA" 1206 3667.24,3169.57 r180 top value=30k
R193 "CRCW120630K0JNEA" 1206 3464.25,3170 r180 top value=30k
R194 "RC0603JR-07560RL" 0603 4326.73,3092.7 r270 top value=560
R195 "CRCW120630K0JNEA" 1206 3670,3535 r180 top value=30k
R196 "CRCW120630K0JNEA" 1206 3474.49,3535 r180 top value=30k
R197 "CRCW060315K0JNEA" 0603 4184.29,3088.07 r270 top value=15k
R198 "RC0603JR-07560RL" 0603 4339.45,3410 r180 top value=560
R199 "CRCW060315K0JNEA" 0603 4172.44,3444.57 r270 top value=15k
R200 "CRCW120630K0JNEA" 1206 3650,3895.31 r180 top value=30k
R200_P "RC1206JR-070RL" 1206 4140,1805 r90 bottom value=0
R201 "CRCW120630K0JNEA" 1206 3449.92,3895.31 r180 top value=30k
R201_P "RC0603FR-072K7L" 0603 4568.5,1195 r180 top value=2.70k
R202 "RC0603JR-07560RL" 0603 4313.54,3790 r270 top value=560
R202_P "ERJ-3RQFR47V" 0603 4860,445 r90 top value=0.47
R203 "CRCW120630K0JNEA" 1206 3646,4337 r180 bottom value=30k
R204 "CRCW120630K0JNEA" 1206 3505,4394.57 r90 bottom value=30k
R205 "CRCW060315K0JNEA" 0603 4183.54,3792.85 r270 top value=15k
R206 "RCS06030000Z0EA" 0603 1612.97,3525.04 r0 top value=0
R207 "RC0603JR-07560RL" 0603 4330.43,4135 r180 top value=560
R208 "CRCW060315K0JNEA" 0603 4175,4167.3 r270 top value=15k
R209 "RCS06030000Z0EA" 0603 1611.47,3595.04 r180 top value=0
R210 "RC0603JR-0710KL" 0603 1945,3355 r180 top value=10k
R211 "RC0603FR-07620RL" 0603 1919.98,3715.04 r180 top value=620
R212 "RC0603FR-07620RL" 0603 5325,3145 r180 top value=620
R213 "RC0603FR-07620RL" 0603 5313.5,3510 r180 top value=620
R214 "RC0603FR-07620RL" 0603 5267.99,3855.31 r180 top value=620
R215 "RC0603FR-07620RL" 0603 5265,4195.31 r180 top value=620
R216 "ERJ-3EKF2002V" 0603 1611.47,3665.04 r0 top value=20.0k
R217 "RC0603FR-07620RL" 0603 1375,3715 r0 top value=620
R218 "RC0603JR-0710KL" 0603 2109.98,3715.04 r0 top value=10k
R219 "ERJ-3EKF2002V" 0603 4960,3260 r0 top value=20.0k
R220 "ERJ-3EKF2002V" 0603 4960,3345 r0 top value=20.0k
R221 "ERJ-3EKF2002V" 0603 4937.44,3983.01 r0 top value=20.0k
R222 "ERJ-3EKF2002V" 0603 4932.44,4073.01 r0 top value=20.0k
R800 "RC0805FR-070RL" FP-RC0805FR-070RL_0805-MFG 3966,3016 r0 bottom value=0
R801 "RC0805FR-070RL" FP-RC0805FR-070RL_0805-MFG 3955,3370 r0 bottom value=0
R802 "RC0805FR-070RL" FP-RC0805FR-070RL_0805-MFG 3946,3727 r0 bottom value=0
R803 "RC0805FR-070RL" FP-RC0805FR-070RL_0805-MFG 3946,4095 r180 bottom value=0
RT1_P "B57153S0479M051" S153 635,2464 r0 top value=4.7
RT2_P "B57153S0479M051" S153 635,1714 r0 top value=4.7
RT3_P "B57153S0479M051" S153 635,989 r0 top value=4.7
T1_P "750320029" FP-750320029_PTH14_32MM25_27MM05-MFG 2810,2114 r0 top value=700µH
TP1_P "5012" Keystone5012 360,2414 r0 top
TP2_P "5012" Keystone5012 360,1689 r0 top
TP3_P "5012" Keystone5012 360,989 r0 top
TP4_P "5010" Keystone5010 4260,1489 r270 top
TP5_P "5012" Keystone5012 360,314 r0 top
TP6_P "5000" Keystone5000 3460,1114 r90 top
TP7_P "5011" Keystone5011 3885,1489 r270 top
TP8_P "5003" Keystone5003 3635,1114 r90 top
TP9_P "5001" Keystone5001 3210,1114 r90 top
TP10_P "TP_SM_1MM" TP_SM_1MM 4410,2035 r90 top
TP11_P "5000" Keystone5000 4260,2514 r0 top
TP12_P "5001" Keystone5001 4060,2514 r0 top
TP13_P "TP_SM_1MM" TP_SM_1MM 3750,604 r90 top
TP14_P "5010" Keystone5010 4485,429 r0 top
TP15_P "TP_SM_1MM" TP_SM_1MM 3955,349 r0 top
TP16_P "5010" Keystone5010 4865,300 r0 top
TP17_P "TP_SM_1MM" TP_SM_1MM 3765,1074 r90 top
TP18_P "TP_SM_1MM" TP_SM_1MM 4537.01,1262.01 r90 top
TP19_P "5010" Keystone5010 4260,1214 r0 top
TP20_P "TP_SM_1MM" TP_SM_1MM 3905,809 r0 top
TP24 "5003" Keystone5003 6520,1320 r0 top
TP25 "5003" Keystone5003 6095,2520 r0 top
TP26 "5003" Keystone5003 6070,1845 r0 top
TP27 "5003" Keystone5003 1070,3705 r90 top
TP28 "5003" Keystone5003 2091.47,3605.04 r90 top
U1_P "UCC24612-1DBVR" DBV0005A_N 3625,1549 r270 bottom
U2_P "FOD817A3SD" N04C 3010,1514 r180 bottom
U3_P "UCC28742DBVR" DBV0006A_N 2035,1989 r180 top
U4_P "TL431AIDBZT" DBZ0003A_N 3335,1084 r270 bottom
U5_P "TL7705AIDR" D0008A_N 4580,2089 r180 bottom
U6_P "ATL431AQDBZR" DBZ0003A_N 5215,2084 r0 bottom
U7_P "TPS65130RGER" RGE0024B 3386,744 r0 top
U8_P "TPS7A3901DSCR" DSC0010J 4280,2269 r90 top
U9_P "TPS563210ADDFR" DDF0008A_N 3885,523.06 r180 top
U10_P "TPS259470ARPWR" RPW0010A-MFG 4635,839 r90 top
U11_P "TPS76318DBVR" DBV0005A_N 4750,574 r0 top
U12_P "TPS55330RTER" RTE0016C_NV 4760,1389 r0 top
U13_P "TPS563210ADDFR" DDF0008A_N 3885,1001.6 r180 top
U14 "FOD817AS" N04C 1310,3010 r0 top
U18 "TLV1805DBVR" DBV0006A_N 6250,2315 r180 top
U19 "ADC122S051QIMMX/NOPB" DGK0008A_N 5865,1240 r90 top
U20 "DRV8220DSG" DSG0008A-MFG 6068.66,6228.35 r270 top
U21 "TLV172IDBVR" FP-DBV0005A-IPC_C 4669.59,5377.4 r180 top
U22 "TLV172IDBVR" FP-DBV0005A-IPC_C 4672.56,4992.98 r180 top
U23 "OPA189IDBVR" DBV0005A_N 4648,5993 r270 top
U24 "OPA189IDBVR" DBV0005A_N 4656,5622 r180 top
U26 "DRV8220DSG" DSG0008A-MFG 5395.71,5902.36 r270 top
U27 "SN74LVC2G74DCUR" FP-DCU0008A-IPC_C 5386.56,5747.96 r0 top
U28 "INA293A1IDBVR" DBV0005A_M 5115.56,6084.96 r90 top
U29 "TLV7011DCKR" DCK0005A_N 5152.56,5802.85 r270 top
U30 "TLV7011DCKR" DCK0005A_N 5622.56,5711.96 r0 top
U32 "MSP430F5131IRSBT" RSB0040B 5241.03,4757.4 r0 top
U33 "ISO1212DBQR" DBQ0016A_N 4637.56,3276.87 r180 top
U34 "ISO1212DBQR" DBQ0016A_N 4605,4005.31 r180 top
U35 "DRV8220DRL" DRL0006A-MFG 1472.34,3584.72 r180 top
U36 "SN74AUP1G08DBVT" DBV0005A_N 1936.47,3465.04 r180 top
Y1 "ABS10-32.768KHZ-1-T" FP-ABS10-MFG 5175.56,5249.96 r0 top

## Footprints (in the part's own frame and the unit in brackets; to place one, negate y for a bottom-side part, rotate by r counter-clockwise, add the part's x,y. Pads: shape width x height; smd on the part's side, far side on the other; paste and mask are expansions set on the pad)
0402 [mm] "0402 from SM-752 data"
  rect 0.8x0.6 smd: 1(-0.6,0) 2(0.6,0)
  silkscreen extent -1.22,-0.52 1.22,0.52, body extent -0.55,-0.3 0.55,0.3, height 0.6
0402S [mil] "Based on C0402S footprint from PADS legacy"
  rect 15x24 smd: 1(-20,0) 2(20,0)
  body extent -22,-12 22,12, height 24
0603 [mm] "0603 from SM-752 data"
  rect 1x0.95 smd: 1(-0.8,0) 2(0.8,0)
  silkscreen extent -1.52,-0.69 1.52,0.69, body extent -0.87,-0.47 0.87,0.47, height 1
0603S [mil]
  rect 20x35 smd: 1(-30,0) 2(30,0)
  body extent -34,-19 34,19, height 39
0805_HV [mil] "0805 with 30mil clearance between pads"
  rect 50x63 smd: 1(-40,0) 2(40,0)
  silkscreen extent -74,-40 74,40, body extent -43,-29 43,29, height 57
1206 [mm] "1206 from SM-752 data"
  rect 1.3x1.85 smd: 1(-1.45,0) 2(1.45,0)
  silkscreen extent -2.4,-1.21 2.4,1.21, body extent -1.7,-0.9 1.7,0.9, height 1.35
1206_180 [mm] "1206_180"
  rect 1.1x1.6 smd: 1(-1.7,0) 2(1.7,0)
  silkscreen extent -0.9,-1 0.9,1, body extent -1.75,-0.95 1.75,0.95, height 1.8
1206_190 [mm] "1206_190"
  rect 1.1x1.6 smd: 1(-1.7,0) 2(1.7,0)
  silkscreen extent -0.9,-1 0.9,1, body extent -1.75,-0.95 1.75,0.95, height 1.9
1206L [mm] "1206 from SM-752 data"
  rect 1.1x1.75 smd: 1(-1.35,0) 2(1.35,0)
  silkscreen extent -0.4,-0.77 0.4,0.77, body extent -1.7,-0.9 1.7,0.9, height 1.35
1210_270 [mm] "1210"
  rect 1.3x2.7 smd: 1(-1.45,0) 2(1.45,0)
  silkscreen extent -2.32,-1.57 2.32,1.57, body extent -1.7,-1.35 1.7,1.35, height 2.7
1812_254 [mm] "SMD, 2-Leads, Body 4.8x3.4mm"
  rect 1.6x3.4 smd: 1(-2,0) 2(2,0)
  silkscreen extent -0.8,-1.7 0.8,1.7, body extent -2.4,-1.7 2.4,1.7, height 2.54
2010 [mm] "Chip Capacitor, Body 5.08x2.54mm, IPC Medium Density"
  rect 1.6x2.7 smd: 1(-2.3,0) 2(2.3,0)
  silkscreen extent -3.42,-1.65 3.42,1.65, body extent -2.73,-1.45 2.73,1.45, height 1.66
2512 [mm] "Chip Resistor, Body 6.3x3.2mm, IPC Medium Density"
  rect 1.3x3.4 smd: 1(-2.95,0) 2(2.95,0)
  silkscreen extent -1.9,-1.6 1.9,1.6, body extent -3.22,-1.67 3.22,1.67, height 0.71
691137710002 [mm] "Horizontal Cable Entry with Pressure Clamp, pitch 5mm, 02p"
  rect 1.95x1.95 hole 1.3: 1(-2.5,0.25)
  round 1.95 hole 1.3: 2(2.5,0.25)
  silkscreen extent -5,-3.75 5,3.75, body extent -5,-3.75 5,3.75, height 11.6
